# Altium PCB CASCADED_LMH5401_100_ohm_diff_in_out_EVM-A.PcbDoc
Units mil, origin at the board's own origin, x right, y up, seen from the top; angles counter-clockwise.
Board outline 1606 x 1500 mil, 6 copper layers (Top Layer L1, Layer 2 GND L2, Layer 3 V+ L3, Layer 4 V- L4, Layer 5 GND L5, Bottom Layer L6), stack 60.4 mil thick; 88 components, 31 nets, 189 pads, 288 vias.
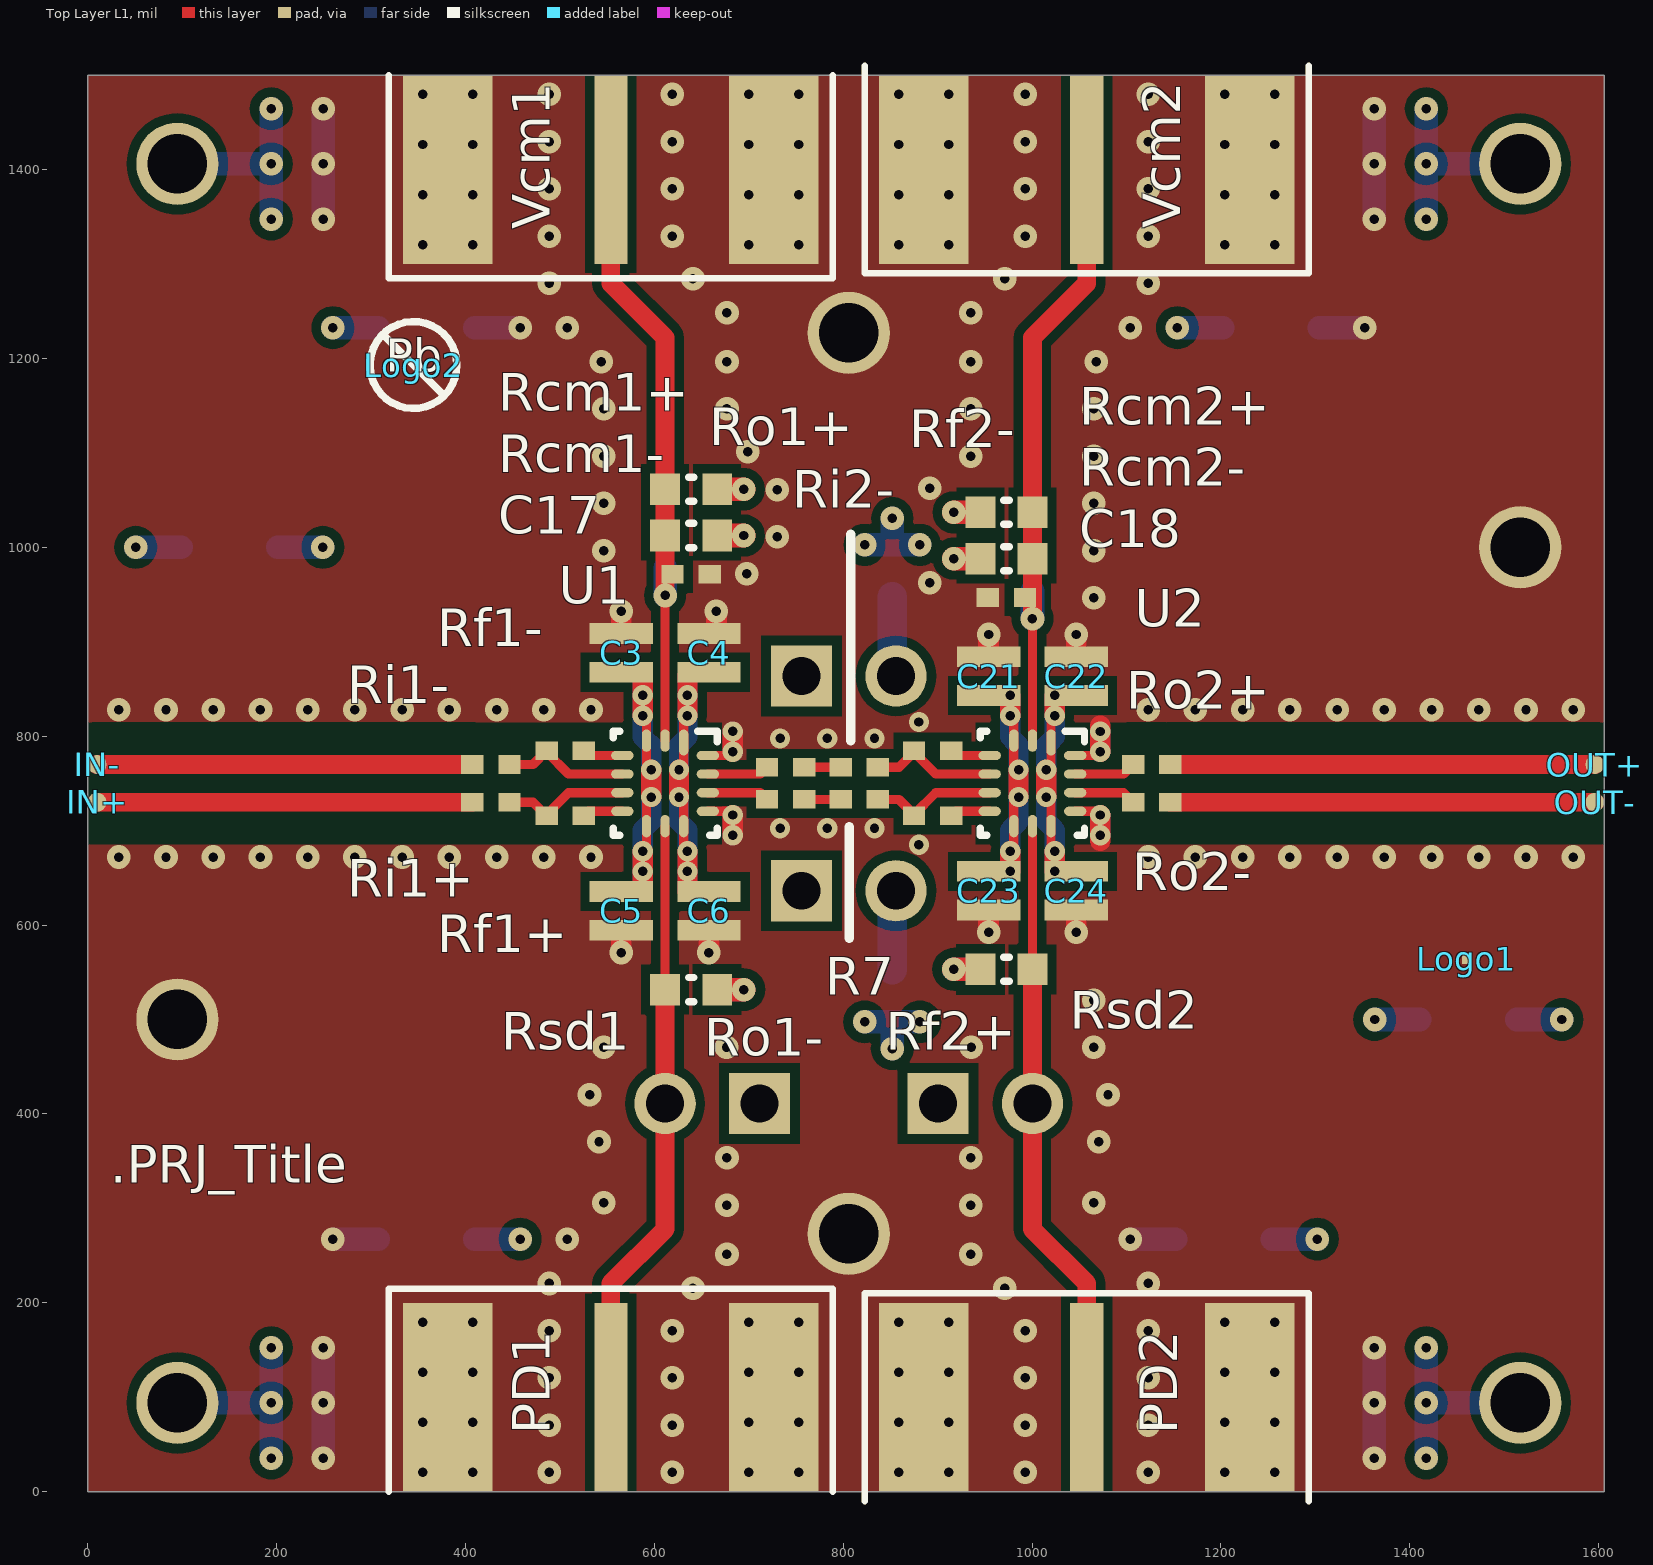
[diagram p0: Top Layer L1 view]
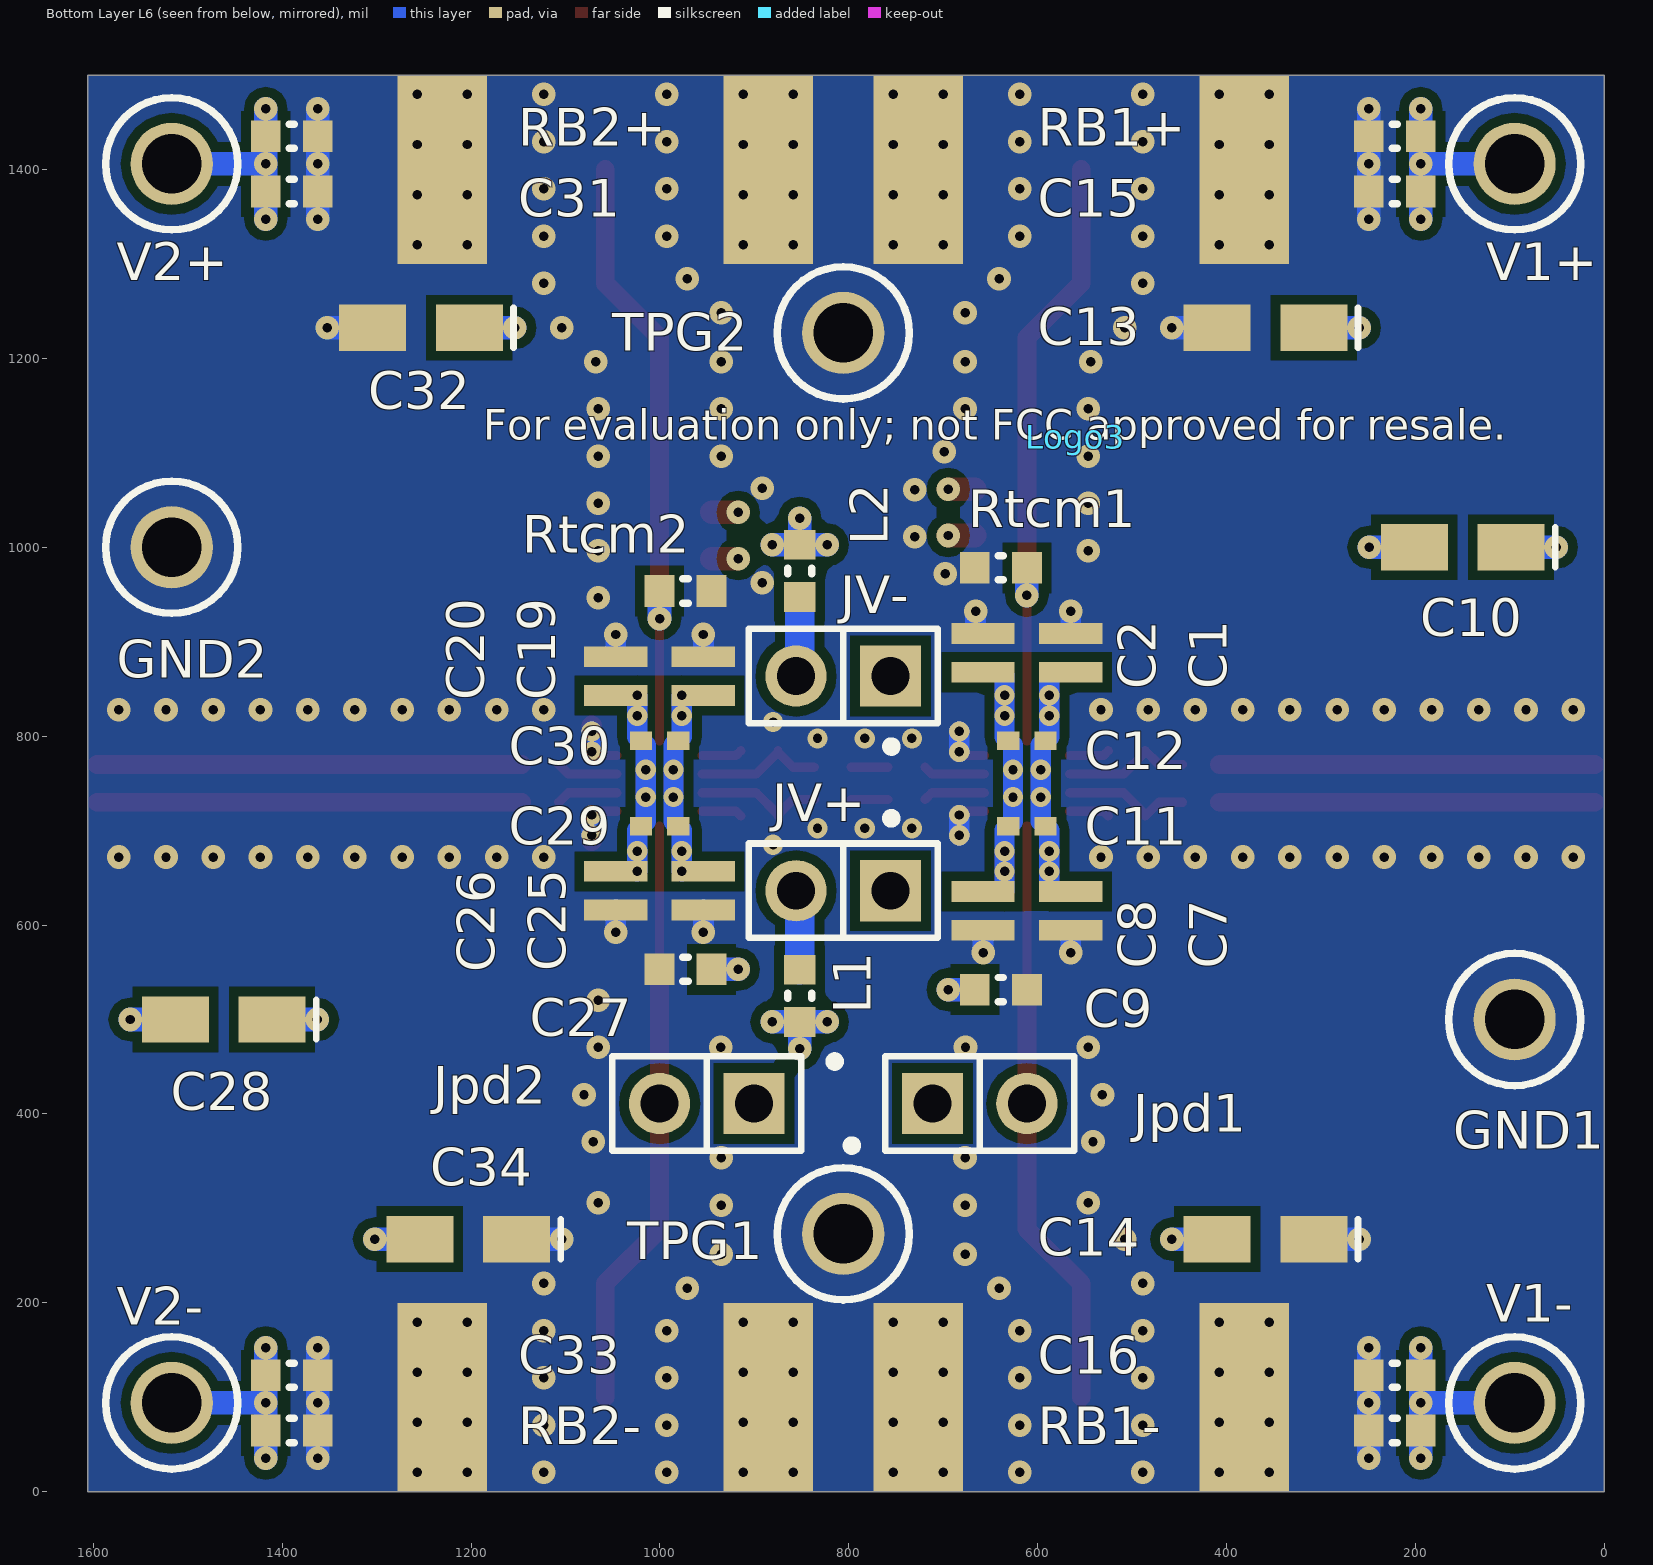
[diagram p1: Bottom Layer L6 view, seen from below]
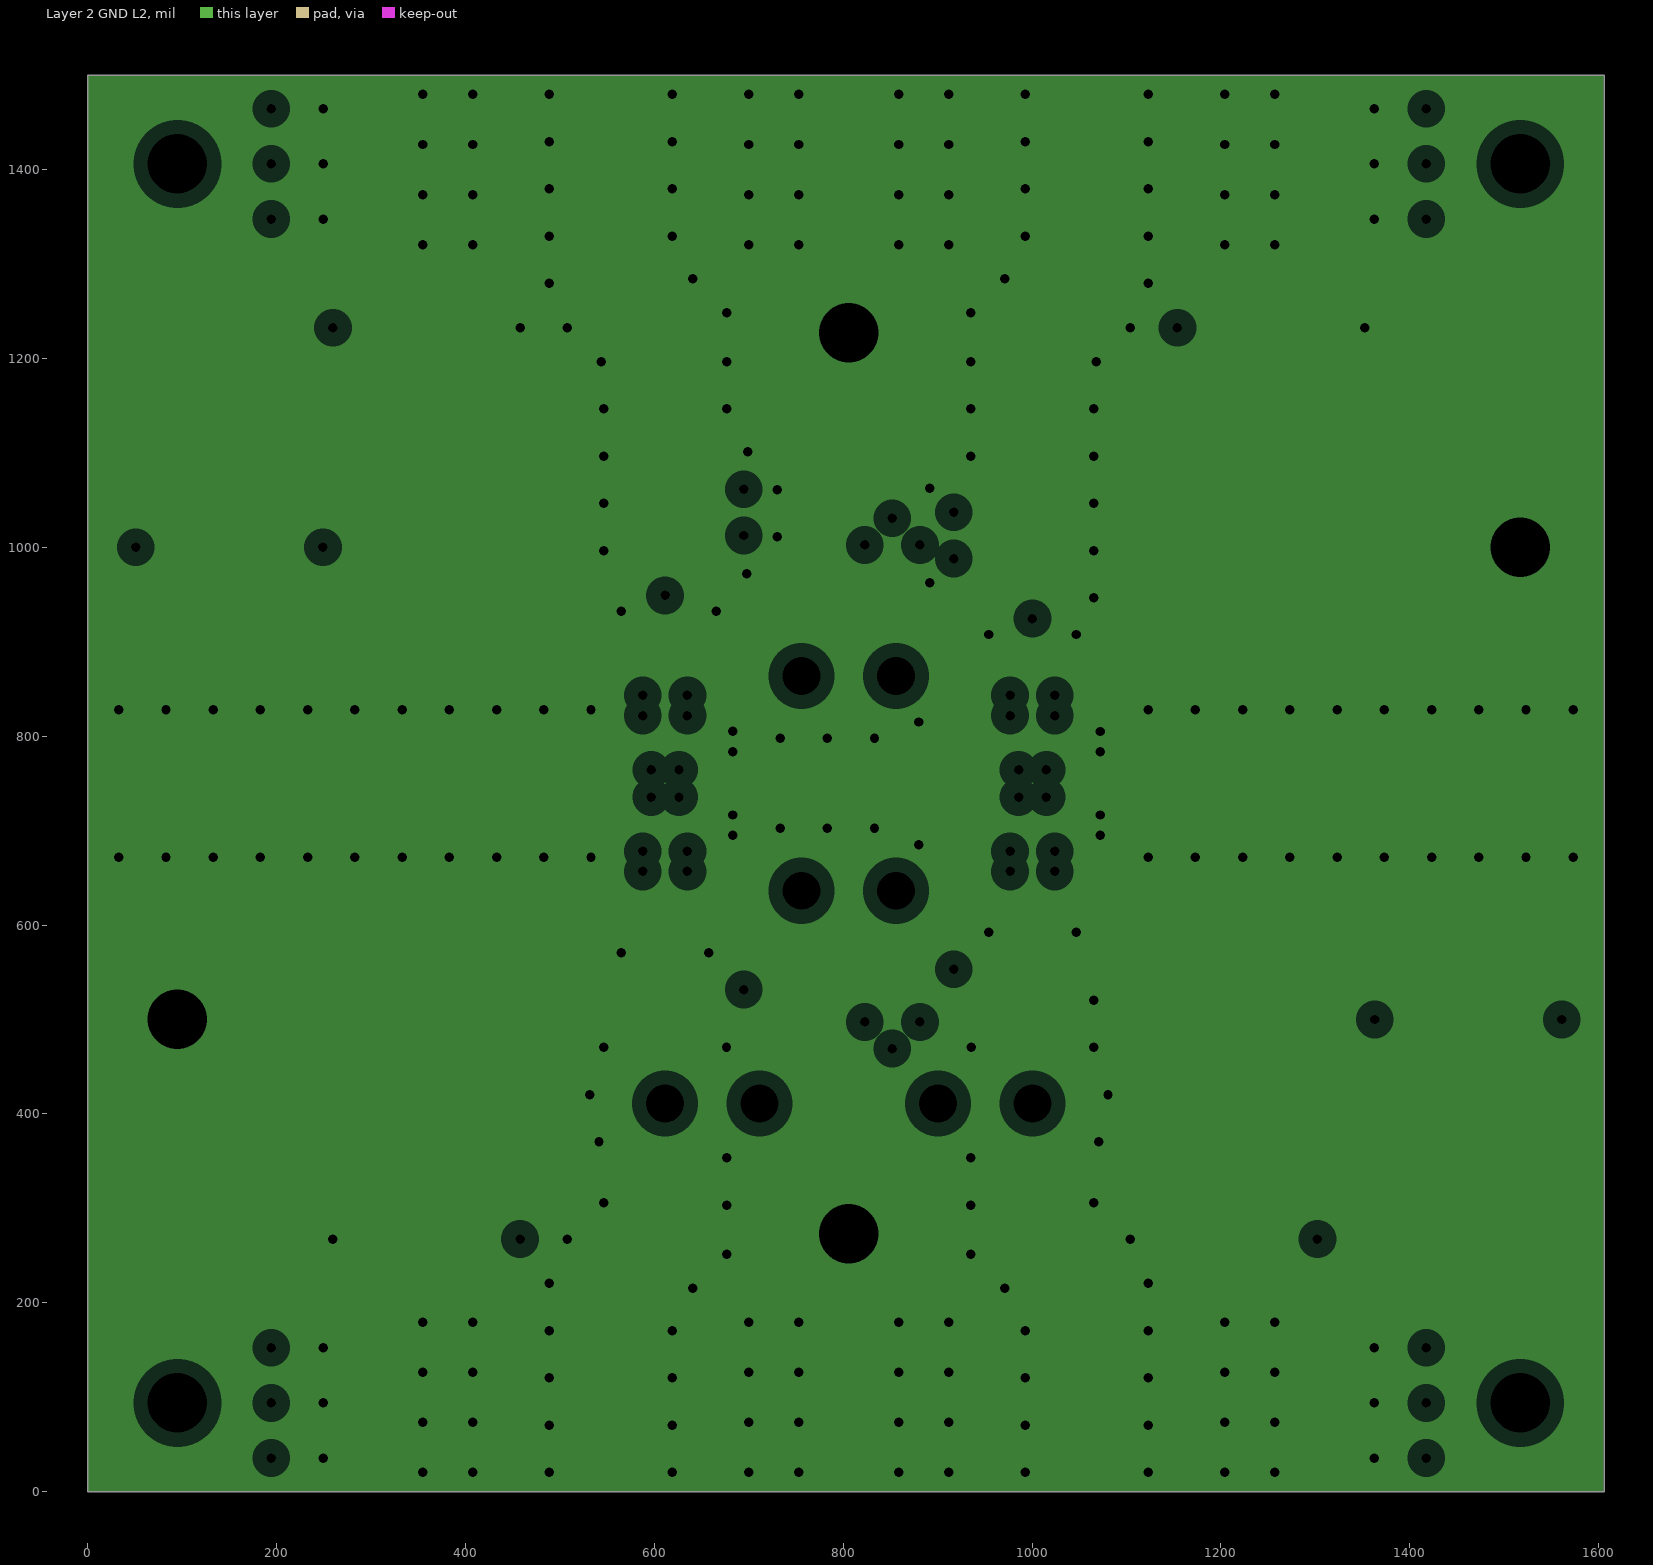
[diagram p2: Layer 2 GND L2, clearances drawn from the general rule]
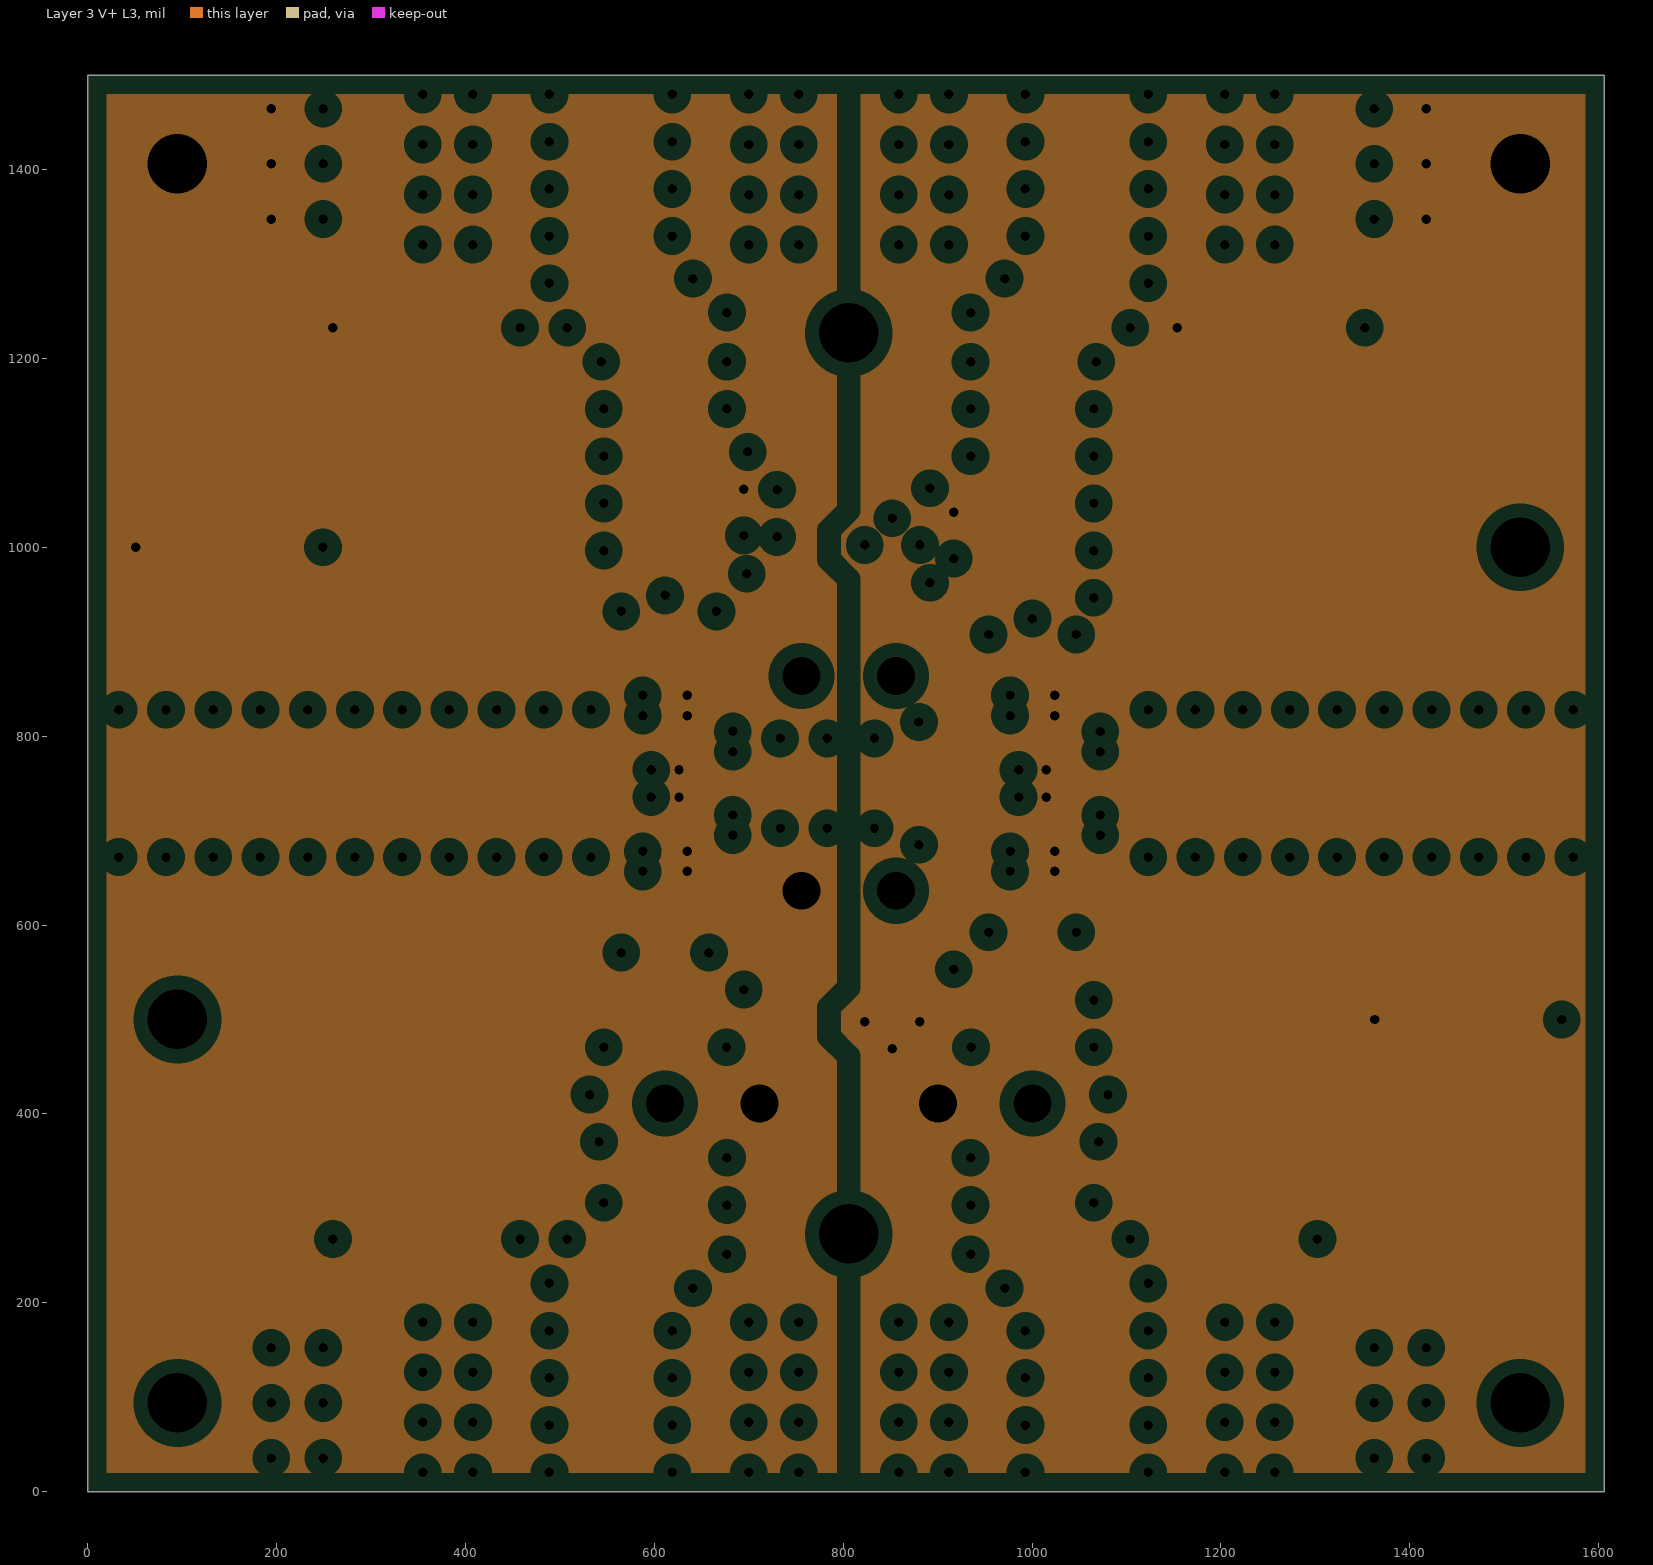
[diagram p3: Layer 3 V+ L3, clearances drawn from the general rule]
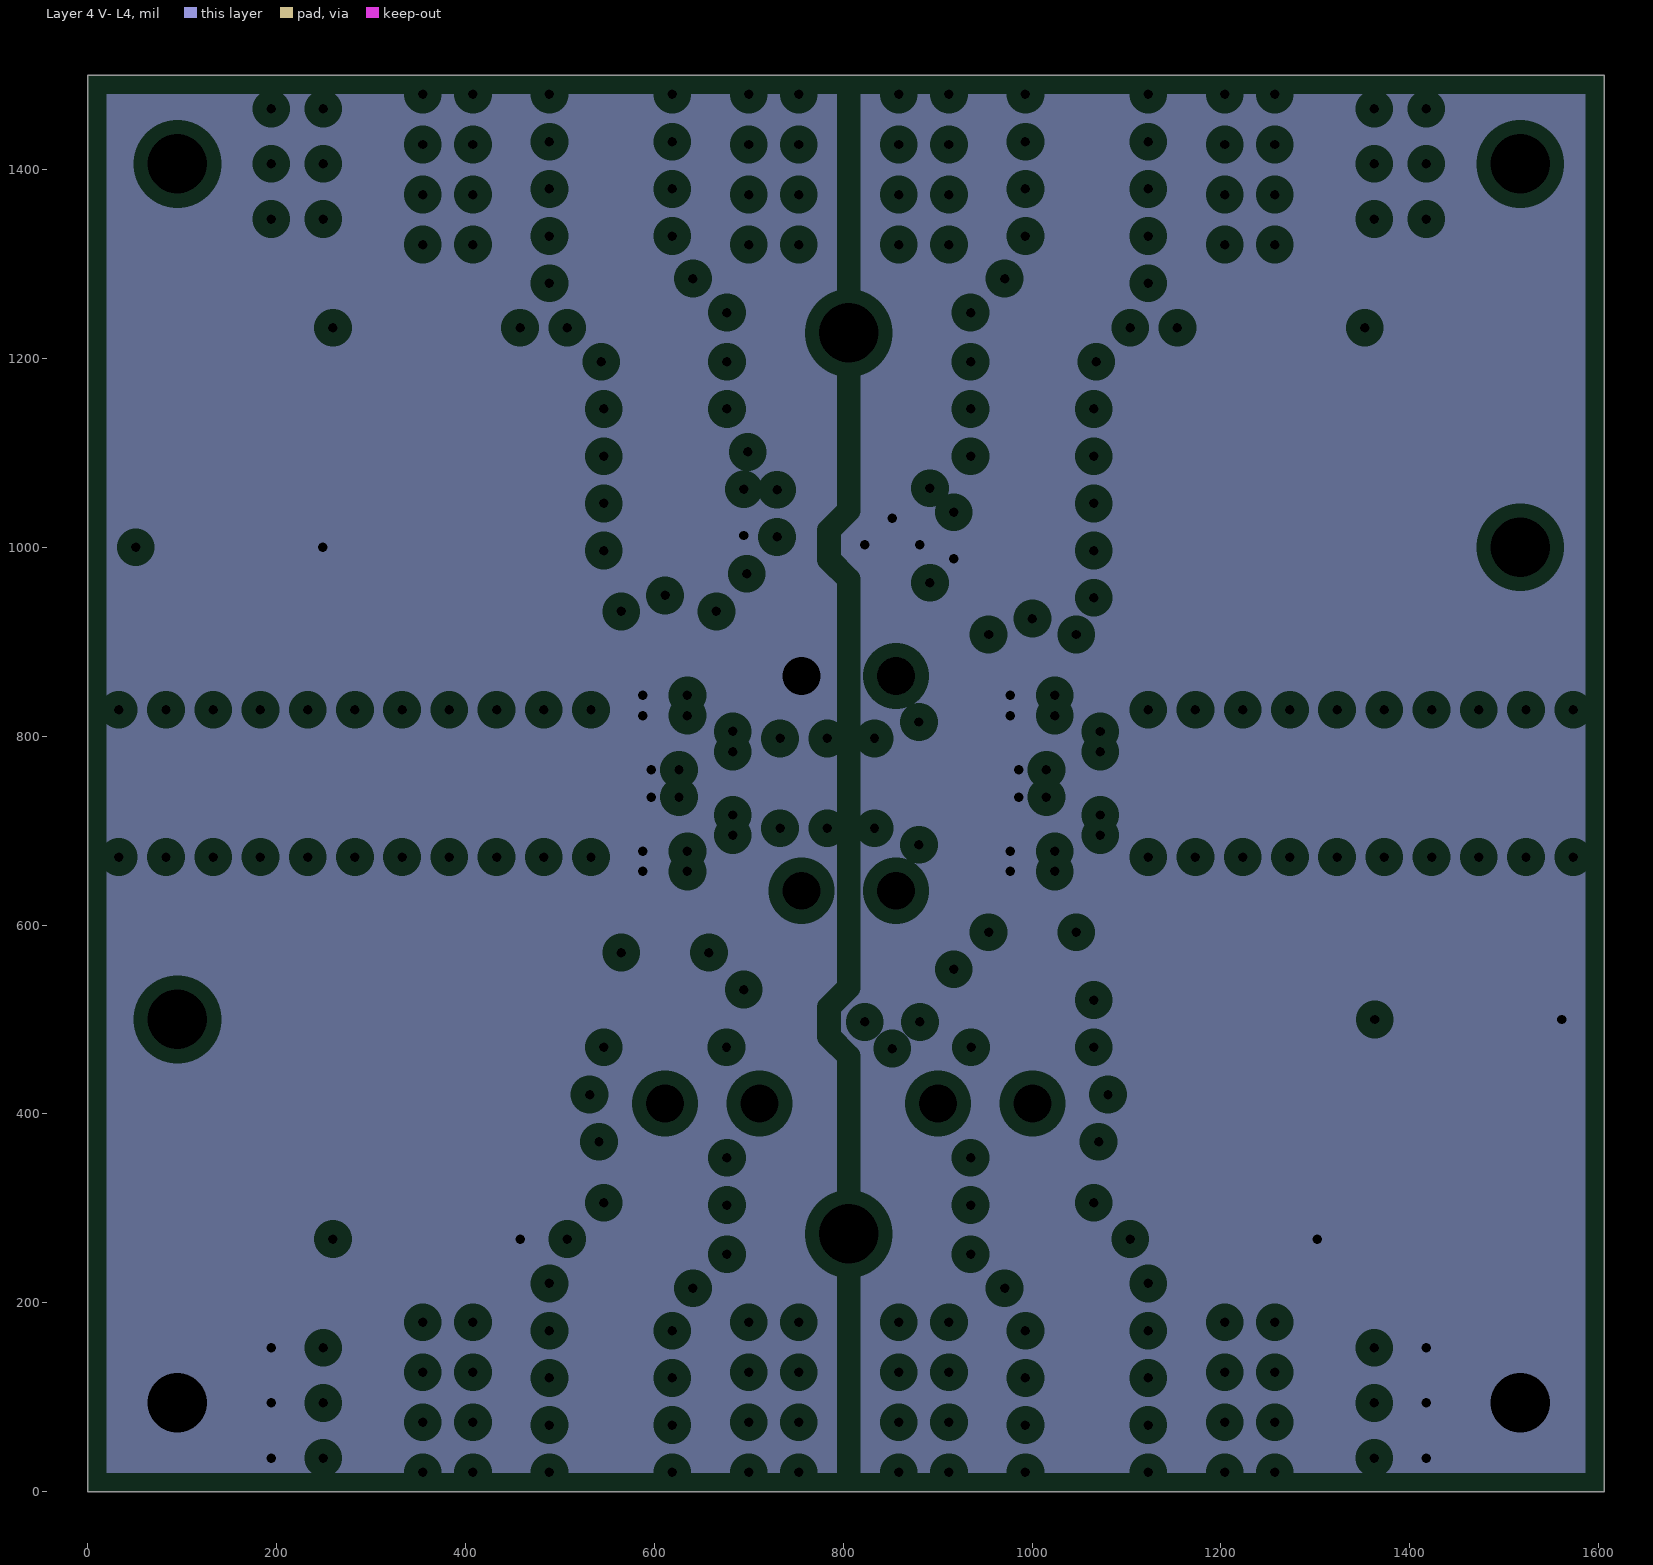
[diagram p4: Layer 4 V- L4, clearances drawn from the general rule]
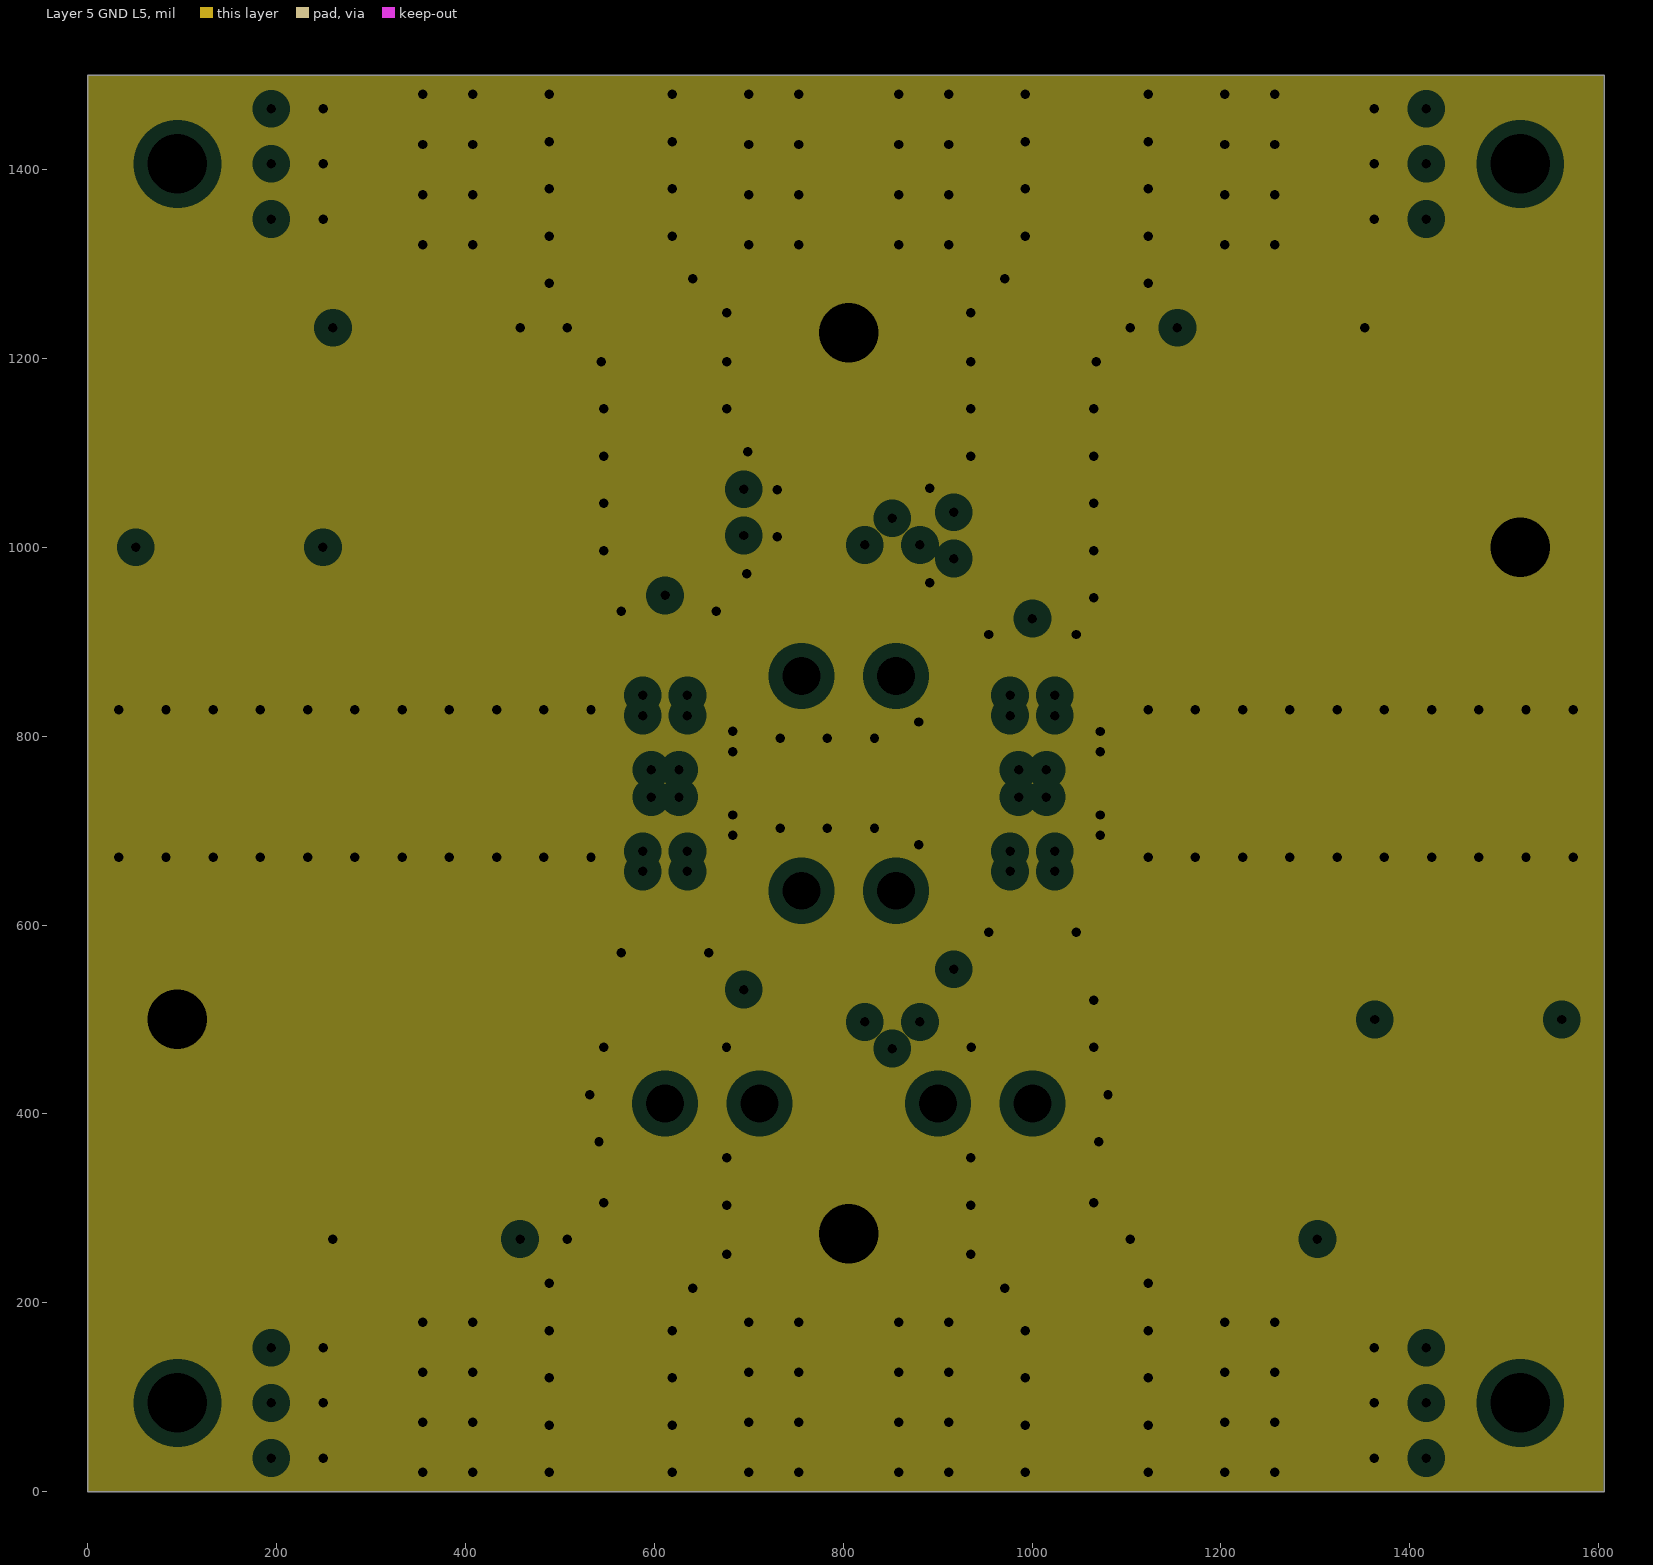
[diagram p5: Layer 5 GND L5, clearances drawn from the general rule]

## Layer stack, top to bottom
Top Solder: solder mask 0.4, Solder Resist, Dk 3.5
Top Layer L1: signal copper 1.4
Dielectric1: core 10, Rogers RO4350, Dk 3.66
Layer 2 GND L2: plane copper 1.4, net GND
Dielectric2: prepreg 10, FR406, Dk 4.8
Layer 3 V+ L3: plane copper 1.4, net (Multiple Nets)
Dielectric3: core 12, FR406, Dk 4.8
Layer 4 V- L4: plane copper 1.4, net (Multiple Nets)
Dielectric4: prepreg 10, FR406, Dk 4.8
Layer 5 GND L5: plane copper 1.4, net GND
Dielectric5: core 10, FR406, Dk 4.8
Bottom Layer L6: signal copper 1.4
Bottom Solder: solder mask 0.4, Solder Resist, Dk 3.5

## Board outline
0,0 1606,0 1606,1500 0,1500

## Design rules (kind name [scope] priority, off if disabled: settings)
AcuteAngle [All] p1: minimum=4.50000000000000E+0001 checktracksonly=FALSE
AssemblyTestPointUsage [All] p1: valid=2
Clearance Clearance_1 [InNamedPolygon('Top Layer L1-GND') vs (InNet('NetIN+_1') OR InNet('NetIN-_1') OR InNet('NetOUT-_1') OR InNet('NetOUT+_1') OR InNet('NetRtcm_1') OR InNet('NetJpd_2'))] p1: gap=35
Clearance Clearance_BoardEdge_MountingHoles [OnCopper and InComponentClass('Mounting Holes') vs IsKeepOut] p2: gap=40
Clearance Clearance_BoardEdge_Poly [OnCopper and InPoly vs IsKeepOut] p3: gap=25
Clearance Clearance_BoardEdge [OnCopper and Not InComponentClass('Logo') and not InComponentClass('FiducialMark') and not InRegion(1000,500,4000,800) and Not IsKeepout vs IsKeepOut] p4: gap=75
Clearance Clearance_Poly [InPolygon] p5: gap=10
Clearance [All] p6: gap=8
ComponentClearance ComponentClearance_Logo [InComponentClass(Logo)] p1: gap=50 collisioncheckmode=3 verticalgap=10 showdistances=FALSE
ComponentClearance ComponentClearance_ScrewToNut [(HasFootprint('NY PMS 440 0025 PH')) vs (HasFootprint('Keystone_1902C'))] p2: gap=5 collisioncheckmode=3 verticalgap=10 showdistances=FALSE
ComponentClearance ComponentClearance_MountingHoles [InComponentClass('Mounting Holes')] p3: gap=250 collisioncheckmode=3 verticalgap=100000 showdistances=FALSE
ComponentClearance ComponentClearance_SmallPassives [HasFootprint('0201*') or HasFootprint('0402*') or HasFootprint('0508') or HasFootprint('0603*') or HasFootprint('0612') or HasFootprint('0805*') or HasFootprint('0815*') or HasFootprint('0830*') or HasFootprint('1206*') or HasFootprint('1210*') or HasFootprint('1808*') or HasFootprint('1812*') or HasFootprint('1825*') or HasFootprint('2010*') or HasFootprint('2220*') or HasFootprint('2225*') or HasFootprint('2512*') or HasFootprint('2728*') or HasFootprint('3518*') or HasFootprint('3216-18*') or HasFootprint('RMS0014A*') or HasFootprint('0306*') or HasFootprint('TP_25MIL-SMT*') vs HasFootprint('0201*') or HasFootprint('0402*') or HasFootprint('0508') or HasFootprint('0603*') or HasFootprint('0612') or HasFootprint('0805*') or HasFootprint('0815*') or HasFootprint('0830*') or HasFootprint('1206*') or HasFootprint('1210*') or HasFootprint('1808*') or HasFootprint('1812*') or HasFootprint('1825*') or HasFootprint('2010*') or HasFootprint('2220*') or HasFootprint('2225*') or HasFootprint('2512*') or HasFootprint('2728*') or HasFootprint('3518*') or HasFootprint('3216-18*') or HasFootprint('RMS0014A*') or HasFootprint('0306*') or HasFootprint('TP_25MIL-SMT*')] p4: gap=10 collisioncheckmode=3 verticalgap=10 showdistances=FALSE
ComponentClearance ComponentClearance_THtoSMT [IsThruComponent vs IsSMTComponent] p5: gap=10 collisioncheckmode=3 verticalgap=0 showdistances=FALSE
ComponentClearance ComponentClearance_THtoTH [IsThruComponent vs IsThruComponent] p6: gap=35 collisioncheckmode=3 verticalgap=0 showdistances=FALSE
ComponentClearance [All] p7: gap=35 collisioncheckmode=3 verticalgap=10 showdistances=FALSE
DiffPairsRouting [All] p1: maxlimit=100 minlimit=10 mostfreqgap=10 toplayer_minwidth=15 toplayer_maxwidth=15 toplayer_prefwidth=15 bottomlayer_minwidth=15 bottomlayer_maxwidth=15 bottomlayer_prefwidth=15 maxuncoupledlength=1000
FabricationTestPointUsage TestPointUsage [All] p1: valid=2 allowmultiple=FALSE
FabricationTestpoint Testpoint [All] p1: side=3 testpointundercomponent=TRUE minsize=40 maxsize=100 preferedsize=60 minholesize=0 maxholesize=40 preferedholesize=32 testpointgrid=1 allowsidetop=TRUE allowsidebottom=TRUE usegrid=TRUE gridtolerance=0.01
FanoutControl Fanout_LCC [IsLCC] p1: bgadir=Out bgaviamode=Centered fanoutstyle=Auto fanoutdirection=Alternating viagrid=1 // Fanout_LCC (Default Rule)
FanoutControl Fanout_BGA [IsBGA] p2: bgadir=Out bgaviamode=Centered fanoutstyle=Auto fanoutdirection=Alternating viagrid=1 // Fanout_BGA (Default Rule)
FanoutControl Fanout_Default [All] p4: bgadir=Out bgaviamode=Centered fanoutstyle=Auto fanoutdirection=Alternating viagrid=1 // Fanout_Default (Default Rule)
FanoutControl Fanout_Small [(CompPinCount < 5)] p5: bgadir=Out bgaviamode=Centered fanoutstyle=Auto fanoutdirection=OutThenIn viagrid=1 // Fanout_Small (Default Rule)
HoleSize [All] p1: absolutevalues=TRUE maxlimit=251 minlimit=8 maxpercent=80.000 minpercent=20.000
MinimumAnnularRing [All] p1: minimumring=5.73
MinimumSolderMaskSliver MinimumSolderMaskSliver_Logo [InComponentClass('Logo') vs InComponentClass('Logo')] p1: minsoldermaskwidth=0.7
MinimumSolderMaskSliver [All] p2: minsoldermaskwidth=3.84
PlaneClearance [All] p1: clearance=15
PlaneConnect [All] p1: planeconnectstyle=Direct reliefexpansion=10 reliefentries=4 reliefconductorwidth=10 reliefairgap=10
PolygonConnect [All] p1: connectstyle=Direct reliefconductorwidth=10 reliefentries=4 polygonreliefangle="90 Angle" airgapwidth=10
RoutingVias [All] p1: holewidth=16 width=34 viastyle="Through Hole" minholewidth=8 minwidth=21.46 maxholewidth=40 maxwidth=65
SMDToCorner [All] p1: distance=30000
SilkToSilkClearance [All] p1: silktosilkclearance=5
SilkToSolderMaskClearance SilkscreenOverComponentPads [IsPad] p1: minsilkscreentomaskgap=5 clearancetoexposedcopper=TRUE
SolderMaskExpansion [All] p1: expansion=3
UnpouredPolygon [All] p1: allowunpoured=FALSE
Width [All] p1: maxlimit=100 minlimit=8 preferedwidth=10 checkconnectedcopper=TRUE
14 further rules are at their usual default settings.

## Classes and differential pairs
component class Header: Jpd1 Jpd2 JV+ JV-
component class 0402L: C12 C17 C18 C30
component class AssemblyNote: ZZ2 ZZ3 ZZ4
component class Logo: Logo1

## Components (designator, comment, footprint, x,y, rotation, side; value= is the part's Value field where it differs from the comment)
C1 "LLL185R71E103MA01L" 0306 565.02,888.1 r270 bottom
C2 "LLL185R71E103MA01L" 0306 657.86,888.1 r90 bottom
C3 "LLL185R71H222MA01L" 0306 565.02,888.1 r90 top
C4 "LLL185R71H222MA01L" 0306 657.86,888.1 r270 top
C5 "LLL185R71H222MA01L" 0306 565.02,614.9 r270 top
C6 "LLL185R71H222MA01L" 0306 657.86,614.9 r90 top
C7 "LLL185R71E103MA01L" 0306 565.02,614.9 r90 bottom
C8 "LLL185R71E103MA01L" 0306 657.86,614.9 r270 bottom
C9 "GRM188R71C103KA01D" 0603L 639,531.67 r180 bottom
C10 "TPSA106K010R0900" 3216-18 150,1000 r0 bottom
C11 "C1005X5R1A104K" 0402L 611.44,704.72 r0 bottom
C12 "C1005X7R1E103K" 0402L 611.44,795.28 r0 bottom
C13 "TPSA106K010R0900" 3216-18 358.83,1232.5 r0 bottom
C14 "TPSA106K010R0900" 3216-18 358.83,267.5 r0 bottom
C15 "Used in BOM report" 0603L 222,1376.77 r0 bottom
C16 "Used in BOM report" 0603L 222,123.23 r0 bottom
C17 "C1005X7R1E103K" 0402L 639,971.33 r180 top
C18 "C1005X7R1E103K" 0402L 972.88,946.87 r0 top
C19 "LLL185R71E103MA01L" 0306 954.02,863.64 r270 bottom
C20 "LLL185R71E103MA01L" 0306 1046.86,863.64 r90 bottom
C21 "LLL185R71H222MA01L" 0306 954.02,863.64 r90 top
C22 "LLL185R71H222MA01L" 0306 1046.86,863.64 r270 top
C23 "LLL185R71H222MA01L" 0306 954.02,636.36 r270 top
C24 "LLL185R71H222MA01L" 0306 1046.86,636.36 r90 top
C25 "LLL185R71E103MA01L" 0306 954.02,636.36 r90 bottom
C26 "LLL185R71E103MA01L" 0306 1046.86,636.36 r270 bottom
C27 "GRM188R71C103KA01D" 0603L 972.88,553.13 r0 bottom
C28 "TPSA106K010R0900" 3216-18 1461.88,500 r0 bottom
C29 "C1005X5R1A104K" 0402L 1000.44,704.72 r0 bottom
C30 "C1005X7R1E103K" 0402L 1000.44,795.28 r0 bottom
C31 "Used in BOM report" 0603L 1389.88,1376.77 r180 bottom
C32 "TPSA106K010R0900" 3216-18 1253.06,1232.5 r0 bottom
C33 "Used in BOM report" 0603L 1389.88,123.23 r180 bottom
C34 "TPSA106K010R0900" 3216-18 1203.06,267.5 r0 bottom
GND1 "5011" Keystone5011 95,500 r180 bottom
GND2 "5011" Keystone5011 1516.88,1000 r0 bottom
IN+ "TESTPOINT" TP_25MIL-SMT 10,730 r90 top
IN- "TESTPOINT" TP_25MIL-SMT 10,770 r90 top
Jpd1 "TSW-102-07-G-S" TSW-102-07-G-S 661.44,411 r180 bottom
Jpd2 "TSW-102-07-G-S" TSW-102-07-G-S 950.44,411 r0 bottom
JV+ "TSW-102-07-G-S" TSW-102-07-G-S 805.94,636.36 r0 bottom
JV- "TSW-102-07-G-S" TSW-102-07-G-S 805.94,863.64 r0 bottom
L1 "BLM18SG331TN1D" 0603L 852,525 r270 bottom
L2 "BLM18SG331TN1D" 0603L 852,975 r90 bottom
Logo1 "Texas Instruments" TI_Symbol_SolderMask_Small 1460,564 r0 top
Logo2 "Pb-Free Symbol" Pb-Free_Overlay_Small 345,1193 r0 top
Logo3 "FCC disclaimer" FCC_disclaimer 560,1117 r180 bottom
OUT+ "TESTPOINT" TP_25MIL-SMT 1596,770 r90 top
OUT- "TESTPOINT" TP_25MIL-SMT 1596,730 r90 top
PD1 "142-0701-851" Emerson_142-0701-851#1 553.94,100 r180 top
PD2 "142-0701-851" Emerson_142-0701-851#2 1057.94,-10 r180 top
R7 "CRCW04020000Z0ED" 0402L 817,733 r180 top
RB1+ "Used in BOM report" 0603L 222,1435.23 r180 bottom
RB1- "Used in BOM report" 0603L 222,64.77 r0 bottom
RB2+ "Used in BOM report" 0603L 1389.88,1435.23 r0 bottom
RB2- "Used in BOM report" 0603L 1389.88,64.77 r180 bottom
Rcm1+ "CRCW06031K00FKEA" 0603L 639,1061.46 r0 top
Rcm1- "CRCW06031K00FKEA" 0603L 639,1012.46 r180 top
Rcm2+ "CRCW06031K00FKEA" 0603L 972.88,1037 r180 top
Rcm2- "CRCW06031K00FKEA" 0603L 972.88,988 r0 top
Rf1+ "CRCW0402174RFKED" 0402L 505.76,715.55 r180 top
Rf1- "CRCW0402174RFKED" 0402L 505.76,784.45 r180 top
Rf2+ "CRCW0402174RFKED" 0402L 894.76,715.55 r180 top
Rf2- "CRCW0402174RFKED" 0402L 894.76,784.45 r180 top
Ri1+ "CRCW040236R5FKED" 0402L 427,730 r180 top
Ri1- "CRCW040236R5FKED" 0402L 427,770 r0 top
Ri2- "CRCW04020000Z0ED" 0402L 817,767 r0 top
Ro1+ "CRCW040240R2FKED" 0402L 739,767 r0 top
Ro1- "CRCW040240R2FKED" 0402L 739,733 r0 top
Ro2+ "CRCW040240R2FKED" 0402L 1126.69,770 r0 top
Ro2- "CRCW040240R2FKED" 0402L 1126.69,730 r0 top
Rsd1 "CRCW060349R9FKEA" 0603L 639,531.67 r180 top
Rsd2 "CRCW060349R9FKEA" 0603L 972.88,553.13 r0 top
Rtcm1 "Used in BOM report" 0603L 639,978.22 r0 bottom
Rtcm2 "Used in BOM report" 0603L 972.88,953.76 r180 bottom
TPG1 "5011" Keystone5011 805.94,273 r180 bottom
TPG2 "5011" Keystone5011 805.94,1227 r180 bottom
U1 "LMH5401IRMSR" RMS0014A 611.44,750 r270 top
U2 "LMH5401IRMSR" RMS0014A 1000.44,750 r270 top
V1+ "5010" Keystone5010 95,1406 r180 bottom
V1- "5014" Keystone5014 95,94 r180 bottom
V2+ "5010" Keystone5010 1516.88,1406 r0 bottom
V2- "5014" Keystone5014 1516.88,94 r180 bottom
Vcm1 "142-0701-851" Emerson_142-0701-851#1 553.94,1400 r0 top
Vcm2 "142-0701-851" Emerson_142-0701-851#2 1057.94,1510 r0 top
ZZ2 "These assemblies are ESD sensitive, ESD precautions shall be observed." AssemblyNote 185,3829.11 r0 top
ZZ3 "These assemblies must be clean and free from flux and all contaminants. Use of no clean flux is not acceptable." AssemblyNote 185,3740.56 r0 top
ZZ4 "These assemblies must comply with workmanship standards IPC-A-610 Class 2., unless otherwise specified." AssemblyNote 185,3652 r0 top

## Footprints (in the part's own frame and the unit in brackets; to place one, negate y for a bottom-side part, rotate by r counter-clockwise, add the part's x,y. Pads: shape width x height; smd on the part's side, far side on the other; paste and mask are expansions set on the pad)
0306 [mil] "bxl footprint"
  rect 22x67 smd: 1(-20.5,0) 2(20.5,0)
  body extent -17,-33 17,33, height 24
0402L [mm] "0402 from SM-752 data"
  rect 0.6x0.5 smd: 1(-0.5,0) 2(0.5,0)
  body extent -0.55,-0.3 0.55,0.3, height 0.6
0603L [mm] "0603 from SM-752 data"
  rect 0.8x0.85 smd: 1(-0.7,0) 2(0.7,0)
  silkscreen extent -0.07,-0.33 0.07,0.33, body extent -0.87,-0.47 0.87,0.47, height 0.85
3216-18 [mm] "Medium density IPC, based on Kemet T495 dimensions"
  rect 1.8x1.25 smd: 1(-1.3,0) 2(1.3,0)
  silkscreen extent -2.49,-0.54 -2.49,0.54, body extent -1.7,-0.9 1.7,0.9, height 1.8
AssemblyNote [mil] "Assembly Note"
Emerson_142-0701-851#1 [mil] "Johnson Components"
  rect 35x200 smd: 1(0,0)
  rect 95x200 smd: 2(-172.5,0) 3(172.5,0)
  rect 95x200 smd far side: 4(172.5,0) 5(-172.5,0)
  silkscreen extent -235,-115 235,100, body extent -190,-95 190,487, height 155
Emerson_142-0701-851#2 [mil] "Johnson Components"
  rect 35x200 smd: 1(0,-110)
  rect 95x200 smd: 2(-172.5,-110) 3(172.5,-110)
  rect 95x200 smd far side: 4(172.5,-110) 5(-172.5,-110)
  silkscreen extent -235,-220 235,0, body extent -190,-195 190,387, height 155
FCC_disclaimer [mil]
Keystone5010 [mil] "Keystone Multipurpose loops"
  round 87 hole 63: 1(0,0)
  silkscreen extent -70,-70 70,70, body extent -63,-63 63,62, height 319
Keystone5011 [mil] "Keystone Multipurpose loops"
  round 87 hole 63: 1(0,0)
  silkscreen extent -70,-70 70,70, body extent -63,-63 63,62, height 319
Keystone5014 [mil] "Keystone Multipurpose loops"
  round 87 hole 63: 1(0,0)
  silkscreen extent -70,-70 70,70, body extent -63,-63 63,62, height 319
Pb-Free_Overlay_Small [mil]
  silkscreen extent -46,-46 46,46
RMS0014A [mm] "QFN, Body 2.6x2.6mm, Pitch 0.5mm"
  oval 0.7x0.25 smd mask+0.066: 1(-1.1,0.5)
  oval 0.6x0.25 smd: 2(-1.15,0) 3(-1.15,-0.5) 8(1.15,-0.5) 9(1.15,0) 10(1.15,0.5)
  oval 0.25x0.6 smd: 4(-0.75,-1.15) 5(-0.25,-1.15) 6(0.25,-1.15) 7(0.75,-1.15) 11(0.75,1.15) 12(0.25,1.15) 13(-0.25,1.15) 14(-0.75,1.15)
  silkscreen extent -1.4,-1.4 1.4,1.4, body extent -1.3,-1.3 1.3,1.3, height 0.61
TI_Symbol_SolderMask_Small [mil]
  rect 10x10 smd paste-10 mask-10: 0(0,0)
TP_25MIL-SMT [mil]
  round 20 smd mask-2.5: 1(0,0)
TSW-102-07-G-S [mm] "Samtec 100mil, 1x2, 230 mil above insulator"
  rect 1.65x1.65 hole 1.016 mask+0: 1(-1.27,0)
  round 1.65 hole 1.016 mask+0: 2(1.27,0)
  silkscreen extent -3.57,-1.27 2.54,1.27, body extent -2.54,-1.27 2.54,1.27, height 8.38

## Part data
C1 C2 C7 C8 C19 C20 C25 C26: "CAP, CERM, 0.01uF, 25V, +/-20%, X7R, 0306"
C3 C4 C5 C6 C21 C22 C23 C24: "CAP, CERM, 2200pF, 50V, +/-20%, X7R, 0306"
C9 C27: "CAP, CERM, 0.01uF, 16V, +/-10%, X7R, 0603"
C10 C13 C14 C28 C32 C34: "CAP, TA, 10uF, 10V, +/-10%, 0.9 ohm, SMD"
C11 C29: "CAP, CERM, 0.1uF, 10V, +/-10%, X5R, 0402"
C12 C17 C18 C30: "CAP, CERM, 0.01uF, 25V, +/-10%, X7R, 0402"
C15 C16 C31 C33: library part Capacitor, "CAP, CERM, xxxF, xxV, [TempCo], xx%, [PackageReference]"
GND1 GND2 TPG1 TPG2: "Test Point, TH, Multipurpose, Black"
IN+ IN- OUT+ OUT-: "TEST POINT.  No entry in BOM."
Jpd1 Jpd2 JV+ JV-: "Header, TH, 100mil, 2x1, Gold plated, 230 mil above insulator"
L1 L2: "Ferrite Bead, 330 ohm @ 100 MHz, 1.5 A, 0603"
Logo1: library part TI_Logo, "Texas Instrument Corporate Signature"
Logo2: library part Pb-Free
Logo3: library part FCC_disclaimer, "FCC_disclaimer"
PD1 PD2 Vcm1 Vcm2: "Connector, SMT, End launch SMA 50 ohm"
R7 Ri2-: "RES, 0, 5%, 0.063 W, 0402"
RB1+ RB1- RB2+ RB2- Rtcm1 Rtcm2: library part Resistor, "RES, xxx ohm, x%, xW, [PackageReference]"
Rcm1+ Rcm1- Rcm2+ Rcm2-: "RES, 1.00k ohm, 1%, 0.1W, 0603"
Rf1+ Rf1- Rf2+ Rf2-: "RES, 174, 1%, 0.063 W, 0402"
Ri1+ Ri1-: "RES, 36.5, 1%, 0.063 W, 0402"
Ro1+ Ro1- Ro2+ Ro2-: "RES, 40.2 ohm, 1%, 0.063W, 0402"
Rsd1 Rsd2: "RES, 49.9 ohm, 1%, 0.1W, 0603"
U1 U2: "8GHz Ultra Wideband Fully Differential Amplifier, RMS0014A"
V1+ V2+: "Test Point, TH, Multipurpose, Red"
V1- V2-: "Test Point, Multipurpose, Yellow, TH"
ZZ2 ZZ3 ZZ4: library part AssemblyNote

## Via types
v1: diameter 25, hole 10, Top Layer L1 to Bottom Layer L6, tented both sides, 248 vias
v2: diameter 21.46, hole 10, Top Layer L1 to Bottom Layer L6, tented both sides, 40 vias

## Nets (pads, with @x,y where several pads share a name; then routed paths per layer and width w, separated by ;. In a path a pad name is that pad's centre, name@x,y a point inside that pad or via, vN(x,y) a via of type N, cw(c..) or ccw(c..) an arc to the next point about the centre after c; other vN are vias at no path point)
GND: C1.1 C2.2 C3.2 C4.1 C5.2 C6.1 C7.1 C8.2 C9.2 C13.2 C14.1 C15.2 C16.2 C17.1 C18.1 C19.1 C20.2 C21.2 C22.1 C23.2 C24.1 C25.1 C26.2 C27.2 C31.2 C32.2 C33.2 C34.1 GND1.1 GND2.1 Logo1.0 PD1.2 PD1.3 PD1.4 PD1.5 PD2.2 PD2.3 PD2.4 PD2.5 RB1+.1 RB1-.2 RB2+.1 RB2-.2 Rtcm1.2 Rtcm2.2 TPG1.1 TPG2.1 U1.11 U1.14 U2.11 U2.14 Vcm1.2 Vcm1.3 Vcm1.4 Vcm1.5 Vcm2.2 Vcm2.3 Vcm2.4 Vcm2.5 | length 1331.2
  Top Layer L1 w9.84: U1.11 679.23,720.47 v2(683.2,716.5) ; U1.14 679.23,779.53 v2(683.2,783.5) ; U2.11 1068.23,720.47 v2(1072.2,716.5) ; U2.14 1068.23,779.53 v2(1072.2,783.5)
  Top Layer L1 w21.46: v2@683.2,695.13 v2(683.2,716.5) ; v2(683.2,783.5) v2@683.2,804.87 ; v2@1072.2,689 v2(1072.2,716.5) ; v2(1072.2,783.5) v2@1072.2,811
  Top Layer L1 w22: v1(565.02,570.9) C5.2 ; C3.2 v1(565.02,932.1) ; v1(657.86,570.9) C6.1 ; C4.1@665.74,908.6 v1(665.74,932.1) ; v1(954.02,592.36) C23.2 ; C21.2 v1(954.02,907.64) ; v1(1046.86,592.36) C24.1 ; C22.1 v1(1046.86,907.64)
  Bottom Layer L6 w21.46: v2@683.2,695.13 v2(683.2,716.5) ; v2(683.2,783.5) v2@683.2,804.87 ; v2@1072.2,695.13 v2(1072.2,716.5) ; v2(1072.2,783.5) v2@1072.2,804.87
  Bottom Layer L6 w22: v1(565.02,570.9) C7.1 ; C1.1 v1(565.02,932.1) ; v1(657.86,570.9) C8.2 ; C2.2@665.74,908.6 v1(665.74,932.1) ; v1(954.02,592.36) C25.1 ; C19.1 v1(954.02,907.64) ; v1(1046.86,592.36) C26.2 ; C20.2 v1(1046.86,907.64)
  Bottom Layer L6 w25: v1(249.56,35.54) RB1-.2 v1(249.56,94) C16.2 v1(249.56,152.46) ; v1(249.56,1347.54) C15.2 v1(249.56,1406) RB1+.1 v1(249.56,1464.46) ; v1(259.71,267.5) C14.1 ; C13.2 v1(457.94,1232.5) ; v1(1103.94,267.5) C34.1 ; C32.2 v1(1352.17,1232.5) ; v1(1362.32,35.54) RB2-.2 v1(1362.32,94) C33.2 v1(1362.32,152.46) ; v1(1362.32,1347.54) C31.2 v1(1362.32,1406) RB2+.1 v1(1362.32,1464.46)
  other v1: 488.94,20.5 618.94,20.5 992.94,20.5 1122.94,20.5 354.94,20.5 407.94,20.5 699.94,20.5 752.94,20.5 858.94,20.5 911.94,20.5 1203.94,20.5 1256.94,20.5 488.94,70.5 618.94,70.5 992.94,70.5 1122.94,70.5 354.94,73.5 407.94,73.5 699.94,73.5 752.94,73.5 858.94,73.5 911.94,73.5 1203.94,73.5 1256.94,73.5 488.94,120.5 618.94,120.5 992.94,120.5 1122.94,120.5 354.94,126.5 407.94,126.5 699.94,126.5 752.94,126.5 858.94,126.5 911.94,126.5 1203.94,126.5 1256.94,126.5 488.94,170.5 618.94,170.5 992.94,170.5 1122.94,170.5 354.94,179.5 407.94,179.5 699.94,179.5 752.94,179.5 858.94,179.5 911.94,179.5 1203.94,179.5 1256.94,179.5 640.94,215.5 970.94,215.5 488.94,220.5 1122.94,220.5 676.94,251.5 934.94,251.5 507.94,267.5 676.94,303.5 934.94,303.5 546.44,306 1065.44,306 676.94,353.5 934.94,353.5 541.44,370.5 1070.44,370.5 531.44,420.5 1080.44,420.5 546.44,470.5 676.44,470.5 935.44,470.5 1065.44,470.5 1065.44,520.5 33,672 83,672 133,672 183,672 233,672 283,672 333,672 383,672 433,672 483,672 533,672 1123,672 1173,672 1223,672 1273,672 1323,672 1373,672 1423,672 1473,672 1523,672 1573,672 33,828 83,828 133,828 183,828 233,828 283,828 333,828 383,828 433,828 483,828 533,828 1123,828 1173,828 1223,828 1273,828 1323,828 1373,828 1423,828 1473,828 1523,828 1573,828 1065.44,946.5 891.88,962.5 698,972 546.44,996.5 1065.44,996.5 730,1011 546.44,1046.5 1065.44,1046.5 730,1061 891.88,1062.5 546.44,1096.5 934.94,1096.5 1065.44,1096.5 699,1101 546.44,1146.5 676.94,1146.5 934.94,1146.5 1065.44,1146.5 543.94,1196.5 676.94,1196.5 934.94,1196.5 1067.94,1196.5 507.94,1232.5 1103.94,1232.5 676.94,1248.5 934.94,1248.5 488.94,1279.5 1122.94,1279.5 640.94,1284.5 970.94,1284.5 354.94,1320.5 407.94,1320.5 699.94,1320.5 752.94,1320.5 858.94,1320.5 911.94,1320.5 1203.94,1320.5 1256.94,1320.5 488.94,1329.5 618.94,1329.5 992.94,1329.5 1122.94,1329.5 354.94,1373.5 407.94,1373.5 699.94,1373.5 752.94,1373.5 858.94,1373.5 911.94,1373.5 1203.94,1373.5 1256.94,1373.5 488.94,1379.5 618.94,1379.5 992.94,1379.5 1122.94,1379.5 354.94,1426.5 407.94,1426.5 699.94,1426.5 752.94,1426.5 858.94,1426.5 911.94,1426.5 1203.94,1426.5 1256.94,1426.5 488.94,1429.5 618.94,1429.5 992.94,1429.5 1122.94,1429.5 354.94,1479.5 407.94,1479.5 488.94,1479.5 618.94,1479.5 699.94,1479.5 752.94,1479.5 858.94,1479.5 911.94,1479.5 992.94,1479.5 1122.94,1479.5 1203.94,1479.5 1256.94,1479.5
  other v2: 880.2,684.98 683.2,695.04 1072.2,695.04 733.2,702.43 783.2,702.43 833.2,702.43 733.2,797.57 783.2,797.57 833.2,797.57 683.2,805.04 1072.2,804.96 880.2,815.02
NetC9_1: C9.1 Rsd1.1 | length 56.5
  Top Layer L1 w25: Rsd1.1 v1(694.81,531.67)
  Bottom Layer L6 w25: C9.1 v1(694.81,531.67)
NetC17_2: C17.2 Rcm1+.1 Rcm1-.2 Rtcm1.1 U1.2 Vcm1.1 | length 655.7
  Top Layer L1 w9.84: U1.2 v1@611.44,946.87
  Top Layer L1 w20: Vcm1.1 553.94,1279.39 611.44,1221.89 Rcm1+.1 v1(611.44,948.99)
  Bottom Layer L6 w25: v1(611.44,948.99) Rtcm1.1
NetC18_2: C18.2 Rcm2+.1 Rcm2-.2 Rtcm2.1 U2.2 Vcm2.1 | length 657.8
  Top Layer L1 w9.84: U2.2 v1(1000.44,924.52)
  Top Layer L1 w20: v1(1000.44,924.52) Rcm2+.1 1000.44,1221.89 1057.94,1279.39 Vcm2.1
  Bottom Layer L6 w25: v1(1000.44,924.52) Rtcm2.1
NetC27_1: C27.1 Rsd2.1 | length 56.5
  Top Layer L1 w25: v1(917.08,553.13) Rsd2.1
  Bottom Layer L6 w25: v1(917.08,553.13) C27.1
NetIN+_1: IN+.1 Ri1+.2 | length 397.3
  Top Layer L1 w20: IN+.1 Ri1+.2
NetIN-_1: IN-.1 Ri1-.1 | length 397.3
  Top Layer L1 w20: IN-.1 Ri1-.1
NetJpd1_2: Jpd1.2 PD1.1 Rsd1.2 U1.9 | length 628.5
  Top Layer L1 w9.84: Rsd1.2 U1.9
  Top Layer L1 w20: PD1.1 553.94,220.61 611.44,278.11 Jpd1.2 Rsd1.2
NetJpd2_2: Jpd2.2 PD2.1 Rsd2.2 U2.9 | length 628.5
  Top Layer L1 w9.84: Rsd2.2 U2.9
  Top Layer L1 w20: Rsd2.2 Jpd2.2 1000.44,278.11 1057.94,220.61 PD2.1
NetJV+_2: JV+.2 L1.1 | length 85.4
  Bottom Layer L6 w31.5: L1.1 852,632.42 JV+.2
NetJV-_2: JV-.2 L2.1 | length 85.4
  Bottom Layer L6 w31.5: L2.1 852,867.58 JV-.2
NetOUT+_1: OUT+.1 Ro2+.2 | length 449.6
  Top Layer L1 w20: Ro2+.2 OUT+.1
NetOUT-_1: OUT-.1 Ro2-.2 | length 449.6
  Top Layer L1 w20: Ro2-.2 OUT-.1
NetR7_1: R7.1 Rf2+.2 U2.6 | length 136.2
  Top Layer L1 w9.84: R7.1 859.16,733 Rf2+.2@875.08,717.08 ; Rf2+.2 Rf2+.2@875.08,717.08 ; U2.6 898.16,740.16 Rf2+.2@875.08,717.08
NetR7_2: R7.2 Ro1-.2 | length 38.6
  Top Layer L1 w9.84: Ro1-.2 R7.2
NetRf1+_1: Rf1+.1 U1.7 | length 42.8
  Top Layer L1 w9.84: Rf1+.1 530.37,720.47 U1.7
NetRf1+_2: Rf1+.2 Ri1+.1 U1.6 | length 136.6
  Top Layer L1 w9.84: Ri1+.1 471.63,730 Rf1+.2 486.08,717.08 509.16,740.16 U1.6
NetRf1-_1: Rf1-.1 U1.4 | length 42.8
  Top Layer L1 w9.84: Rf1-.1 530.37,779.53 U1.4
NetRf1-_2: Rf1-.2 Ri1-.2 U1.5 | length 136.6
  Top Layer L1 w9.84: Ri1-.2 471.63,770 Rf1-.2 486.08,782.92 509.16,759.84 U1.5
NetRf2+_1: Rf2+.1 U2.7 | length 42.8
  Top Layer L1 w9.84: Rf2+.1 919.37,720.47 U2.7
NetRf2-_1: Rf2-.1 U2.4 | length 42.8
  Top Layer L1 w9.84: Rf2-.1 919.37,779.53 U2.4
NetRf2-_2: Rf2-.2 Ri2-.2 U2.5 | length 136.2
  Top Layer L1 w9.84: Ri2-.2 859.16,767 Rf2-.2@875.08,782.92 ; Rf2-.2 Rf2-.2@875.08,782.92 ; U2.5 898.16,759.84 Rf2-.2@875.08,782.92
NetRi2-_1: Ri2-.1 Ro1+.2 | length 38.6
  Top Layer L1 w9.84: Ro1+.2 Ri2-.1
NetRo1+_1: Ro1+.1 U1.13 | length 65.6
  Top Layer L1 w9.84: U1.13 712.16,759.84 Ro1+.1
NetRo1-_1: Ro1-.1 U1.12 | length 65.6
  Top Layer L1 w9.84: U1.12 712.16,740.16 Ro1-.1
NetRo2+_1: Ro2+.1 U2.13 | length 65.5
  Top Layer L1 w9.84: U2.13 1096.85,759.84 Ro2+.1
NetRo2-_1: Ro2-.1 U2.12 | length 65.5
  Top Layer L1 w9.84: U2.12 1096.85,740.16 Ro2-.1
V1+: C2.1 C4.2 C6.2 C8.1 C10.1 C11.2 C12.2 C13.1 C15.1 Jpd1.1 JV+.1 RB1+.2 Rcm1+.2 U1.1 U1.10 V1+.1 | length 904.4
  Top Layer L1 w9.84: v2(626.17,735.53) 631.13,730.58 U1.10 631.13,682.21 v2(635.09,678.24) ; v2(626.17,764.47) 631.13,769.42 631.13,817.79 v2(635.09,821.76)
  Top Layer L1 w19.68: C6.2@635.09,635.4 C6.2 ; C4.2@635.09,867.6 C4.2
  Top Layer L1 w21.46: v2(626.17,735.53) v2(626.17,764.47) ; C6.2@635.09,635.32 v2@635.09,656.7 ; v2@635.09,656.86 v2(635.09,678.24) ; v2(635.09,821.76) v2@635.09,843.14 ; v2(635.09,843.22) C4.2@635.09,864.6
  Top Layer L1 w25: Rcm1+.2 v1(694.81,1061.46)
  Bottom Layer L6 w19.68: C8.1@635.09,635.4 C8.1 ; C2.1@635.09,867.6 C2.1
  Bottom Layer L6 w21.46: C8.1@635.09,635.49 635.09,656.86 v2(635.09,678.24) 635.09,700.76 C11.2 626.17,709.68 v2(626.17,735.53) v2(626.17,764.47) 626.17,790.32 C12.2 635.09,799.24 v2(635.09,821.76) v2@635.09,843.14 ; v2(635.09,843.22) C2.1@635.09,864.6
  Bottom Layer L6 w25: v1(50.89,1000) C10.1 ; V1+.1 v1(194.44,1406) ; v1(194.44,1347.54) C15.1 v1(194.44,1406) ; v1(194.44,1464.46) RB1+.2 v1(194.44,1406) ; v1(259.71,1232.5) C13.1
  other v2: 635.09,656.78
V1-: C1.2 C3.1 C5.1 C7.2 C10.2 C11.1 C12.1 C14.2 C16.1 JV-.1 RB1-.1 Rcm1-.1 U1.3 U1.8 V1-.1 | length 904.4
  Top Layer L1 w9.84: v2(587.79,678.24) 591.76,682.21 U1.8 591.76,730.58 v2(596.71,735.53) ; v2(587.79,821.76) 591.76,817.79 U1.3 591.76,769.42 v2(596.71,764.47)
  Top Layer L1 w19.68: C5.1 C5.1@587.79,635.4 ; C3.1 C3.1@587.79,867.6
  Top Layer L1 w21.46: C5.1@587.79,635.32 v2@587.79,656.7 ; v2@587.79,656.86 v2(587.79,678.24) ; v2(587.79,821.76) v2@587.79,843.14 ; v2(587.79,843.22) C3.1@587.79,864.6 ; v2(596.71,735.53) v2(596.71,764.47)
  Top Layer L1 w25: Rcm1-.1 v1(694.81,1012.46)
  Bottom Layer L6 w19.68: C7.2 C7.2@587.79,635.4 ; C1.2 C1.2@587.79,867.6
  Bottom Layer L6 w21.46: C7.2@587.79,635.49 587.79,656.86 v2(587.79,678.24) 587.79,700.76 C11.1 596.71,709.68 v2(596.71,735.53) v2(596.71,764.47) 596.71,790.32 C12.1 587.79,799.24 v2(587.79,821.76) v2@587.79,843.14 ; v2(587.79,843.22) C1.2@587.79,864.6
  Bottom Layer L6 w25: V1-.1 v1(194.44,94) ; v1(194.44,35.54) RB1-.1 v1(194.44,94) ; v1(194.44,152.46) C16.1 v1(194.44,94) ; C10.2 v1(249.11,1000) ; C14.2 v1(457.94,267.5)
  other v2: 587.79,656.78
V2+: C20.1 C22.2 C24.2 C26.1 C28.1 C29.2 C30.2 C31.1 C32.1 Jpd2.1 L1.2 RB2+.2 Rcm2+.2 U2.1 U2.10 V2+.1 | length 905.6
  Top Layer L1 w9.84: v2(1015.17,735.53) 1020.13,730.58 U2.10 1020.13,682.21 v2(1024.09,678.24) ; v2(1015.17,764.47) 1020.13,769.42 1020.13,795.28 1020.13,817.79 v2(1024.09,821.76)
  Top Layer L1 w19.68: C24.2@1024.09,656.86 C24.2 ; C22.2@1024.09,843.14 C22.2
  Top Layer L1 w21.46: v2(1015.17,735.53) v2(1015.17,764.47) ; C24.2@1024.09,656.86 v2(1024.09,678.24) ; v2(1024.09,821.76) C22.2@1024.09,843.14
  Top Layer L1 w25: v1(917.07,1037) Rcm2+.2
  Bottom Layer L6 w19.68: C26.1@1024.09,656.86 C26.1 ; C20.1@1024.09,843.14 C20.1
  Bottom Layer L6 w21.46: C26.1@1024.09,656.86 v2(1024.09,678.24) 1024.09,700.76 C29.2 1015.17,709.68 v2(1015.17,735.53) v2(1015.17,764.47) 1015.17,790.32 C30.2 1024.09,799.24 v2(1024.09,821.76) C20.1@1024.09,843.14
  Bottom Layer L6 w25: v1(822.77,497.44) L1.2 ; v1@852.06,469.19 L1.2 ; v1(881.23,497.44) L1.2 ; v1(1153.94,1232.5) C32.1 ; v1(1362.77,500) C28.1 ; v1(1417.44,1347.54) C31.1 v1(1417.44,1406) ; v1(1417.44,1464.46) RB2+.2 v1(1417.44,1406) ; V2+.1 v1(1417.44,1406)
  other v1: 852,469.19
  other v2: 1024.09,656.78 1024.09,843.22
V2-: C19.2 C21.1 C23.1 C25.2 C28.2 C29.1 C30.1 C33.1 C34.2 L2.2 RB2-.1 Rcm2-.1 U2.3 U2.8 V2-.1 | length 905.6
  Top Layer L1 w9.84: v2(976.79,678.24) 980.76,682.21 U2.8 980.76,730.58 v2(985.71,735.53) ; v2(976.79,821.76) 980.76,817.79 U2.3 980.76,769.42 v2(985.71,764.47)
  Top Layer L1 w19.68: C23.1 C23.1@976.79,656.86 ; C21.1 C21.1@976.79,843.14
  Top Layer L1 w21.46: C23.1@976.79,656.86 v2(976.79,678.24) ; v2(976.79,821.76) C21.1@976.79,843.14 ; v2(985.71,735.53) v2(985.71,764.47)
  Top Layer L1 w25: v1(917.07,988) Rcm2-.1
  Bottom Layer L6 w19.68: C25.2 C25.2@976.79,656.86 ; C19.2 C19.2@976.79,843.14
  Bottom Layer L6 w21.46: C25.2@976.79,656.86 v2(976.79,678.24) 976.79,700.76 C29.1 985.71,709.68 v2(985.71,735.53) v2(985.71,764.47) 985.71,790.32 C30.1 976.79,799.24 v2(976.79,821.76) C19.2@976.79,843.14
  Bottom Layer L6 w25: v1(822.77,1002.56) L2.2 ; v1@851.94,1030.81 L2.2 ; v1(881.23,1002.56) L2.2 ; C34.2 v1(1302.17,267.5) ; v1(1417.44,35.54) RB2-.1 v1(1417.44,94) ; v1(1417.44,152.46) C33.1 v1(1417.44,94) ; C28.2 v1(1561,500) ; V2-.1 v1(1417.44,94)
  other v1: 852,1030.81
  other v2: 976.79,656.78 976.79,843.22

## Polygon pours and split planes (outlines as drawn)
GND on Top Layer L1 "Top Layer L1-GND" (solid, remove dead copper, pour order 3): 0,0 0,1500 1606,1500 1606,0
GND on Bottom Layer L6 "Bottom Layer L6-GND" (solid, remove dead copper, pour order 4): 0,0 0,1500 1606,1500 1606,0
GND on Layer 2 GND L2 (split plane): 1605.95,0.05 0.05,0.05 0.05,1499.95 1605.95,1499.95
V2+ on Layer 3 V+ L3 (split plane): 1585.9,20.1 818.5,20.1 818.5,461.06 818.26,463.51 817.55,465.87 816.38,468.04 814.82,469.94 797.56,487.2 797.56,507.68 814.82,524.94 816.38,526.84 817.55,529.02 818.26,531.37 818.5,533.82 818.5,966.18 818.26,968.63 817.55,970.98 816.38,973.16 814.82,975.06 797.56,992.32 797.56,1012.8 814.82,1030.06 816.38,1031.96 817.55,1034.13 818.26,1036.49 818.5,1038.94 818.5,1479.9 1585.9,1479.9
V1+ on Layer 3 V+ L3 (split plane): 793.38,1044.14 776.12,1026.88 774.56,1024.98 773.4,1022.81 772.68,1020.45 772.44,1018 772.44,987.12 772.68,984.67 773.4,982.31 774.56,980.14 776.12,978.24 793.38,960.97 793.38,539.03 776.12,521.76 774.56,519.86 773.4,517.69 772.68,515.33 772.44,512.88 772.44,482 772.68,479.55 773.4,477.19 774.56,475.02 776.12,473.12 793.38,455.86 793.38,20.1 20.1,20.1 20.1,1479.9 793.38,1479.9
V2- on Layer 4 V- L4 (split plane): 1585.9,20.1 818.5,20.1 818.5,461.06 818.26,463.51 817.55,465.87 816.38,468.04 814.82,469.94 797.56,487.2 797.56,507.68 814.82,524.94 816.38,526.84 817.55,529.02 818.26,531.37 818.5,533.82 818.5,966.18 818.26,968.63 817.55,970.98 816.38,973.16 814.82,975.06 797.56,992.32 797.56,1012.8 814.82,1030.06 816.38,1031.96 817.55,1034.13 818.26,1036.49 818.5,1038.94 818.5,1479.9 1585.9,1479.9
V1- on Layer 4 V- L4 (split plane): 793.38,1044.14 776.12,1026.88 774.56,1024.98 773.4,1022.81 772.68,1020.45 772.44,1018 772.44,987.12 772.68,984.67 773.4,982.31 774.56,980.14 776.12,978.24 793.38,960.97 793.38,539.03 776.12,521.76 774.56,519.86 773.4,517.69 772.68,515.33 772.44,512.88 772.44,482 772.68,479.55 773.4,477.19 774.56,475.02 776.12,473.12 793.38,455.86 793.38,20.1 20.1,20.1 20.1,1479.9 793.38,1479.9
GND on Layer 5 GND L5 (split plane): 1605.95,0.05 0.05,0.05 0.05,1499.95 1605.95,1499.95

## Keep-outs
Keep-Out Layer:
  text ".Layer_Name" at 577,-858.49 h60

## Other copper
Top Layer L1:
  pour cut-out: 1157.76,814.84 1157.76,685.16 939.88,685.16 939.88,814.84
  pour cut-out: 454.13,814.84 454.13,685.16 672,685.16 672,814.84
  text ".Layer_Name" at 577,-858.49 h60
Bottom Layer L6:
  text ".Layer_Name" at 577,-858.49 h60
Layer 2 GND L2 (plane layer: these items are gaps in the copper):
  text ".Layer_Name" at 577,-858.49 h60
Layer 3 V+ L3 (plane layer: these items are gaps in the copper):
  lines w25: 805.94,0 805.94,461.06 785,482 785,512.88 805.94,533.82 805.94,966.18 785,987.12 785,1018 805.94,1038.94 805.94,1500
  text ".Layer_Name" at 577,-858.49 h60
Layer 4 V- L4 (plane layer: these items are gaps in the copper):
  lines w10: 0,1500 1606,1500
  lines w25: 805.94,0 805.94,461.06 785,482 785,512.88 805.94,533.82 805.94,966.18 785,987.12 785,1018 805.94,1038.94 805.94,1500
  text ".Layer_Name" at 577,-858.49 h60
Layer 5 GND L5 (plane layer: these items are gaps in the copper):
  text ".Layer_Name" at 577,-858.49 h60

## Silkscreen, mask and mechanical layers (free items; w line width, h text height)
Top Overlay:
  lines w10: 806.23,586 806.23,704 ; 808.23,795 808.23,1014
  text ".PRJ_Title" at 24,327 h40
  text ".Layer_Name" at 577,-858.49 h60
Bottom Overlay:
  text ".Layer_Name" at 577,-858.49 h60
Top Paste:
  text ".Layer_Name" at 577,-858.49 h60
Bottom Paste:
  text ".Layer_Name" at 577,-858.49 h60
Top Solder:
  lines w9.84: 875.08,717.08 898.16,740.16 955.17,740.16 ; 875.08,782.92 898.16,759.84 955.17,759.84
  lines w10.84: 486.08,717.08 509.16,740.16 566.17,740.16 ; 486.08,782.92 509.16,759.84 566.17,759.84 ; 875.08,717.08 898.16,740.16 955.17,740.16 ; 875.08,782.92 898.16,759.84 955.17,759.84
  lines w15.84: 486.08,715.55 486.08,717.08 ; 486.08,782.92 486.08,784.45 ; 656.72,740.16 712.16,740.16 719.32,733 ; 656.72,759.84 712.16,759.84 719.32,767 ; 758.69,733 797.31,733 ; 758.69,767 797.32,767 ; 836.68,733 859.16,733 875.08,717.08 ; 836.69,767 859.16,767 875.08,782.92 ; 1045.72,740.16 1096.85,740.16 1107.01,730 ; 1045.72,759.84 1096.85,759.84 1107.01,770
  lines w26: 10,730 407.31,730 ; 10,770 407.31,770 ; 1146.38,730 1596,730 ; 1146.38,770 1596,770
  text ".Layer_Name" at 577,-858.49 h60
  text ".Layer_Name" at 577,-858.49 h60
Bottom Solder:
  text ".Layer_Name" at 577,-858.49 h60
Drill Guide:
  text ".Layer_Name" at 577,-858.49 h60
M1 Board Outline:
  the board outline again, w10
  text ".Layer_Name" at 577,-858.49 h60
M2 Board Dimensions:
  rectangle: 124.5,-410.5 499.5,-285.5
  rectangle: -0.5,-285.5 124.5,-160.5
  lines w7: -0.5,-285.5 999.5,-285.5 ; 124.5,-410.5 124.5,-160.5 ; 249.5,-410.5 249.5,-160.5 ; 499.5,-410.5 499.5,-160.5 ; 749.5,-410.5 749.5,-160.5 ; -0.5,-410.5 -0.5,-160.5 999.5,-160.5 999.5,-410.5 -0.5,-410.5
  lines w10: -0.5,-475.5 -0.5,-455.5 ; 59.5,-485.5 -0.5,-465.5 ; 59.5,-445.5 -0.5,-465.5 ; 223.58,-465.5 -0.5,-465.5 ; 775.42,-465.5 999.5,-465.5 ; 939.5,-485.5 999.5,-465.5 ; 939.5,-445.5 999.5,-465.5 ; 999.5,-475.5 999.5,-455.5
  text "1000 (mil)" at 233.58,-501.49 h60
  text ".Layer_Name" at 577,-858.49 h60
M3 3D STEP Top:
  text ".Layer_Name" at 577,-858.49 h60
M4 3D STEP Bottom:
  text ".Layer_Name" at 577,-858.49 h60
M5 Assembly Top:
  lines w10: -292,-930.17 6308,-930.17 ; -292,-726.83 6310,-726.83 ; -292,-523.5 -292,-1133.5 3713,-1133.5 6310,-1133.5 6310,-523.5 -291.5,-523.5 -291.5,-1133.5 1284,-1133.5 ; 2173,-1133.5 2173,-523.5 ; 3440,-726.83 3440,-523.5 ; 4280,-726.83 4280,-523.5 ; 4902,-1140 4902,-937.17
  text "COMPONENTS MARKED 'DNP' SHOULD NOT BE POPULATED." at 1153.5,-318.5 h60
  text "ASSEMBLY VARIANT:" at 1153,-434 h60
  text ".VariantName" at 2189,-434 h60
  text "PCB VIEWED FROM TOP SIDE" at -228.5,-655.67 h60
  text "BOARD #:" at 2248,-655.67 h60
  text ".PRJ_Number" at 2793.5,-655.67 h60
  text "REV:" at 3638,-655.67 h60
  text ".PCB_Rev" at 3929.5,-655.67 h60
  text "SVN REV:" at 4476,-655.67 h60
  text ".VersionControl_RevNumber" at 4982,-655.67 h60
  text "IGNORE ->" at -228.5,-858.49 h60
  text "PLOT NAME =" at -228.5,-1064.34 h60
  text ".plot_File_Name" at 577,-1064.34 h60
  text "GENERATED    :" at 2250,-1064.34 h60
  text ".Print_Date" at 3119.5,-1064.34 h60
  text ".Print_Time" at 3848.5,-1064.34 h60
  text "TEXAS INSTRUMENTS" at 5113,-1064.34 h60
M6 Assembly Bottom:
  lines w10: -292.5,-727.33 6309.5,-727.33 ; -290.5,-930.67 6309.5,-930.67 ; 1115.5,-1140.5 1115.5,-937.67 ; 1737.5,-727.33 1737.5,-524 ; 2577.5,-727.33 2577.5,-524 ; 3844.5,-1134 3844.5,-524 ; 4733.5,-1134 6309,-1134 6309,-524 -292.5,-524 -292.5,-1134 2304.5,-1134 6309.5,-1134 6309.5,-524
  text "COMPONENTS MARKED 'DNP' SHOULD NOT BE POPULATED." at 6102,-318 h60
  text ".VariantName" at 5058,-434 h60
  text "ASSEMBLY VARIANT:" at 6097,-434 h60
  text ".VersionControl_RevNumber" at 1035.5,-656.17 h60
  text "SVN REV:" at 1541.5,-656.17 h60
  text ".PCB_Rev" at 2088,-656.17 h60
  text "REV:" at 2379.5,-656.17 h60
  text ".PRJ_Number" at 3224,-656.17 h60
  text "BOARD #:" at 3769.5,-656.17 h60
  text "PCB VIEWED FROM BOTTOM SIDE" at 6246,-656.17 h60
  text "IGNORE ->" at 2547.85,-858.49 h60
  text "TEXAS INSTRUMENTS" at 904.5,-1064.84 h60
  text ".Print_Time" at 2169,-1064.84 h60
  text ".Print_Date" at 2898,-1064.84 h60
  text "GENERATED    :" at 3767.5,-1064.84 h60
  text ".plot_File_Name" at 5440.5,-1064.84 h60
  text "PLOT NAME =" at 6246,-1064.84 h60
M9 Title Sheet:
  drawing of 57 lines, arcs and shapes, not listed
  text "1" at 739.84,8036.5 h70
  text "2" at 3235.5,8036.5 h70
  text "3" at 5724.84,8036.5 h70
  text "4" at 8231.51,8036.5 h70
  text "5" at 10730.5,8036.5 h70
  text "6" at 13235.5,8036.5 h70
  text "A" at -416.5,6893.5 h70
  text "A" at 14383.5,6893.5 h70
  text "B" at -416.5,4513.5 h70
  text "B" at 14383.5,4513.5 h70
  text "C" at -416.5,2138.5 h70
  text "C" at 14383.5,2138.5 h70
  text "PROJECT TITLE:" at 11343.5,277.5 h45
  text ".PRJ_Title" at 11393.5,144.17 h70
  text "DESIGNED FOR:" at 11343.5,-23.5 h45
  text ".PRJ_Customer" at 11393.5,-163.5 h70
  text "D" at -416.5,-231.5 h70
  text "D" at 14383.5,-231.5 h70
  text "FILE NAME:" at 11343.5,-323.5 h45
  text ".PCB_File_Name_No_Path" at 11393.5,-443.5 h70
  text "Texas Instruments (TI) and/or its licensors do not warrant the accuracy or completeness of this specification" at 6374,-605.34 h45
  text "ENGINEER:" at 11343.5,-613.5 h45
  text "LAYOUT BY:" at 12848.5,-613.5 h45
  text "or any information contained therein. TI and/or its licensors do not warrant that this design will meet" at 6329.01,-718 h45
  text ".PRJ_Engineer" at 11393.5,-768.49 h70
  text ".PCB_Layout" at 12899,-768.49 h70
  text "the specifications, will be suitable for your application or fit for any particular purpose, or will operate in" at 6329.01,-830.67 h45
  text ".Layer_Name" at 577,-858.49 h60
  text "ALTIUM DESIGNER VERSION:" at 12848.5,-923.5 h45
  text "an implementation. TI and/or its licensors do not warrant that the design is production worthy. You should" at 6329.01,-943.33 h45
  text "completely validate and test your design implementation to confirm the system functionality for your application." at 6374,-1056 h45
  text ".print_Scale" at 11393.5,-1056.83 h70
  text ".Application_BuildNumber" at 12899,-1056.83 h70
  text "1" at 739.84,-1263.5 h70
  text "2" at 3235.5,-1263.5 h70
  text "3" at 5724.84,-1263.5 h70
  text "4" at 8231.51,-1263.5 h70
  text "5" at 10730.5,-1263.5 h70
  text "6" at 13235.5,-1263.5 h70
M10 Fab Notes:
  drawing of 212 lines, arcs and shapes, not listed
  text "DESIGN INFORMATION" at 12381.02,6810 h60
  text "(REFER ALSO ARRAY/PANEL PROFILING INFORMATION)" at 12019.46,6648.29 h60
  text "BOARD SIZE" at 11333.46,6644 h60
  text "X" at 12301.46,6516.18 h60
  text "Number of Layers :" at 11736.46,6319 h60
  text "6" at 12831.27,6309 h60
  text "MIN. TRACK WIDTH:" at 11736.46,6180 h60
  text "8" at 12832.7,6180 h60
  text "MIL" at 12987.46,6180 h60
  text "MIN. CLEARANCE:" at 11736.46,6048 h60
  text "8" at 12832.7,6048 h60
  text "MIL" at 12987.46,6048 h60
  text "MIN. VIA PAD SIZE:" at 11736.46,5916 h60
  text "21" at 12802.71,5916 h60
  text "MIL" at 12987.46,5916 h60
  text "0.05mm (2MIL)" at 12431.46,5774.29 h60
  text "MINIMUM ANNULAR RING" at 11407.23,5770 h60
  text "EXTERNAL" at 13139.46,5770 h60
  text "PER" at 11607.23,5652 h60
  text "IPC-D-275 CLASS 2 LEVEL C" at 11827.23,5652 h60
  text "MIL, HOLES" at 13315.46,5539.71 h60
  text "+/-" at 12923,5539 h60
  text "+/-" at 13777,5539 h60
  text "REGISTRATION TOLERANCES:" at 11407.23,5534 h60
  text "METAL" at 12607,5534 h60
  text "5" at 13183.2,5534 h60
  text "3" at 14016.2,5534 h60
  text "MIL" at 14132.46,5534 h60
  text "MATERIAL:" at 11332.46,5324.54 h60
  text "FR-4 High Tg" at 12318.9,5184.21 h60
  text "FR-408" at 11753.46,5175.64 h60
  text "X" at 12165.46,5175.64 h60
  text "X" at 13054.46,5176 h60
  text "OTHER   ROGERS 4350" at 13241.46,5175.64 h60
  text "OTHER" at 13241.46,5175.64 h60
  text "62 MIL (1.6mm) +/-10%" at 12073.56,5012.92 h60
  text "THICKNESS:" at 11407.23,5008.64 h60
  text "X" at 11945.4,5008.64 h60
  text "OTHER" at 13358.46,5008.64 h60
  text "TOLERANCE:" at 11407.23,4850.64 h60
  text "X" at 12246.53,4850.64 h60
  text "ANSI IPC-6012 TYPE 3 CLASS 2" at 12433.48,4850.64 h60
  text "OTHER +/-" at 12433.46,4694.64 h60
  text "BOW & TWIST:" at 11407.23,4537.64 h60
  text "X" at 12246.53,4537.64 h60
  text "ANSI IPC-6012 TYPE 3 CLASS 2" at 12433.48,4537.64 h60
  text "OTHER +/-" at 12433.46,4379.13 h60
  text "COPPER THICKNESS (FINISHED):" at 11332.46,4243.64 h60
  text "1.4MIL (1oz)" at 12212.46,4090.92 h60
  text "2MIL (1.4oz)" at 12979.46,4090.92 h60
  text "2.8MIL (2oz)" at 13706.46,4090.92 h60
  text "OUTER:" at 11689.46,4086.64 h60
  text "X" at 12084,4086 h60
  text "1.4MIL (1oz)" at 12212.46,3933.92 h60
  text "2.8MIL (2oz)" at 12979.46,3933.92 h60
  text "N/A" at 13706,3934.29 h60
  text "INNER SIGNAL:" at 11400.38,3929.64 h60
  text "X" at 12085.42,3929.64 h60
  text "DRILLING:" at 11332.46,3790.64 h60
  text "REFERENCE:" at 11407.23,3673.64 h60
  text "X" at 12055.46,3673.64 h60
  text "AS SHOWN" at 12242.46,3673.64 h60
  text "X" at 12956.46,3673.64 h60
  text "NC_DRILL FILES" at 13093.46,3673.64 h60
  text "PTH MIN COPPER THICKNESS:" at 11407.23,3515.64 h60
  text "X" at 12757.46,3515.64 h60
  text "1MIL" at 12894.46,3515.64 h60
  text "OTHER" at 13391.46,3515.64 h60
  text "BOARD FINISH:" at 11332.46,3356.64 h60
  text "SILKSCREEN:" at 11487.68,3238.64 h60
  text "X" at 12436.46,3238.64 h60
  text "TOP" at 12562.46,3238.64 h60
  text "X" at 12946.46,3238.64 h60
  text "BOTTOM" at 13073.46,3238.64 h60
  text "SILKSCREEN COLOR:" at 11487.68,3071.64 h60
  text "X" at 12435.42,3071.64 h60
  text "WHITE" at 12562.46,3071.64 h60
  text "OTHER" at 13073.46,3071.64 h60
  text "SOLDER RESIST COLOR:" at 11487.68,2901.64 h60
  text "X" at 12055.42,2742.44 h60
  text "GREEN" at 12182.46,2742.44 h60
  text "BLUE" at 12773.46,2742.44 h60
  text "OTHER" at 13311.46,2742.44 h60
  text "IMMERSION GOLD (ENIG)" at 12393.46,2553.92 h60
  text "ENEPIG" at 13731,2550.64 h60
  text "SURFACE FINISH:" at 11332.46,2549.64 h60
  text "X" at 12206.51,2549.64 h60
  text "IMM. TIN/SILVER OR EQUIV" at 11662,2392.64 h60
  text "OTHER" at 13093.46,2392.64 h60
  text "ARRAY/PANEL:" at 11332.46,2213.64 h60
  text "X" at 12206.46,2213.64 h60
  text "CUT AND TRIM PER MECH LAYER 1" at 12393.46,2209.35 h60
  text "N.C. ROUTE" at 12393.46,2057.64 h60
  text "V. SCORE" at 13259.46,2057.64 h60
  text "CERTIFICATION:" at 11332.46,1920.64 h60
  text "MATERIALS AND WORKMANSHIP FOR ALL PCBS" at 12057.46,1920.64 h60
  text "TO MEET OR EXCEED THE REQUIREMENTS OF:" at 12057.46,1822.64 h60
  text "X" at 11683.96,1686.13 h60
  text "ANSI IPC-A-600F CLASS ->" at 11822.96,1686.13 h60
  text "X" at 13462.02,1686.13 h60
  text "2" at 13580.96,1686.14 h60
  text "1" at 13265.96,1684.64 h60
  text "3" at 13934.96,1684.64 h60
  text "X" at 11686.02,1526.64 h60
  text "UL 94V-0" at 11822.96,1526.64 h60
  text "X" at 12498.02,1526.64 h60
  text "RoHS" at 12634.96,1526.64 h60
  text "OTHER" at 13279.36,1526.64 h60
  text "PER ORDER" at 13676.42,1526.64 h60
  text "Single ended tracks 50 ohms Top Layer equal 35mils width." at 2594,1500 h100
  text "ADDITIONAL REQUIREMENTS:" at 11332.46,1385.64 h60
  text "MICROSECTION:" at 11407.23,1270.64 h60
  text "YES" at 12312.96,1270.64 h60
  text "REQUIRED" at 13174.46,1114.49 h60
  text "BARE BOARD ELEC. TEST:" at 11407.23,1111.64 h60
  text "NONE" at 12712.96,1111.64 h60
  text "X" at 13047.46,1111.64 h60
  text "PER ORDER" at 13766.46,1111.64 h60
  text "MANUFACTURER'S UL:" at 11407.23,954.64 h60
  text "RAIL" at 12572.96,950.35 h60
  text "METAL" at 13064.77,950.35 h60
  text "X" at 13440,950 h60
  text "SILK" at 13576.46,950.35 h60
  text ".Layer_Name" at 577,-858.49 h60
M11 Gerber Information:
  lines w10: -292,-930.17 6308,-930.17 ; -292,-726.83 6310,-726.83 ; -292,-523.5 -292,-1133.5 3713,-1133.5 6310,-1133.5 6310,-523.5 -291.5,-523.5 -291.5,-1133.5 1284,-1133.5 ; 2173,-1133.5 2173,-523.5 ; 3440,-726.83 3440,-523.5 ; 4280,-726.83 4280,-523.5 ; 4902,-1140 4902,-937.17
  text "ALL ARTWORK VIEWED FROM TOP SIDE" at -228.5,-655.67 h60
  text "BOARD #:" at 2248,-655.67 h60
  text ".PRJ_Number" at 2793.5,-655.67 h60
  text "REV:" at 3638,-655.67 h60
  text ".PCB_Rev" at 3929.5,-655.67 h60
  text "SVN REV:" at 4476,-655.67 h60
  text ".VersionControl_RevNumber" at 4982,-655.67 h60
  text "LAYER NAME =" at -228.5,-858.49 h60
  text "PLOT NAME =" at -228.5,-1064.34 h60
  text ".plot_File_Name" at 577,-1064.34 h60
  text "GENERATED    :" at 2250,-1064.34 h60
  text ".Print_Date" at 3119.5,-1064.34 h60
  text ".Print_Time" at 3848.5,-1064.34 h60
  text "TEXAS INSTRUMENTS" at 5113,-1064.34 h60
M12 Stackup:
  lines w5: 11362,7748.1 14230,7748.1 ; 11362,7843.3 14230,7843.3 ; 11302,6967 ccw(c11333,6967) 11333,6936 14259,6936 ccw(c14259,6967) 14290,6967 14290,7917 ccw(c14259,7917) 14259,7948 11333,7948 ccw(c11333,7917) 11302,7917 11302,6967
  text "Layer Stack Up Detail for: CASCADED_LMH5401_EVM-A.PcbDoc" at 11362,7866.15 h40
  text "Layer" at 11362,7807.8 h22
  text "Gerber" at 11973.83,7807.8 h22
  text "Copper" at 12285.82,7807.8 h22
  text "Dielectric" at 12633.74,7807.8 h22
  text "Dielectric" at 12997.05,7807.8 h22
  text "Dielectric" at 13453.93,7807.8 h22
  text "Dielectric" at 13817.24,7807.8 h22
  text "Name" at 11362,7763.8 h22
  text "Document" at 11973.83,7763.8 h22
  text "Thickness" at 12285.82,7763.8 h22
  text "Height" at 12633.74,7763.8 h22
  text "Material" at 12997.05,7763.8 h22
  text "Constant" at 13453.93,7763.8 h22
  text "Type" at 13817.24,7763.8 h22
  text "Top Solder Mask" at 11362,7701.33 h31
  text "(.GTS)" at 11973.83,7701.33 h31
  text "0.4mil" at 12633.74,7701.33 h31
  text "Solder Resist" at 12997.05,7701.33 h31
  text "3.50" at 13453.93,7701.33 h31
  text "Top Layer L1" at 11362,7612.77 h31
  text "(.GTL)" at 11973.83,7612.77 h31
  text "1.4mil" at 12285.82,7612.77 h31
  text "10mil" at 12633.74,7568.5 h31
  text "Rogers RO4350" at 12997.05,7568.5 h31
  text "3.66" at 13453.93,7568.5 h31
  text "Core" at 13817.24,7568.5 h31
  text "Layer 2 GND L2" at 11362,7524.23 h31
  text "(.GP1)" at 11973.83,7524.23 h31
  text "1.4mil" at 12285.82,7524.23 h31
  text "10mil" at 12633.74,7479.95 h31
  text "FR406" at 12997.05,7479.95 h31
  text "4.80" at 13453.93,7479.95 h31
  text "PrePreg" at 13817.24,7479.95 h31
  text "Layer 3 V+ L3" at 11362,7435.67 h31
  text "(.GP2)" at 11973.83,7435.67 h31
  text "1.4mil" at 12285.82,7435.67 h31
  text "12mil" at 12633.74,7391.4 h31
  text "FR406" at 12997.05,7391.4 h31
  text "4.80" at 13453.93,7391.4 h31
  text "Core" at 13817.24,7391.4 h31
  text "Layer 4 V- L4" at 11362,7347.12 h31
  text "(.GP3)" at 11973.83,7347.12 h31
  text "1.4mil" at 12285.82,7347.12 h31
  text "10mil" at 12633.74,7302.85 h31
  text "FR406" at 12997.05,7302.85 h31
  text "4.80" at 13453.93,7302.85 h31
  text "PrePreg" at 13817.24,7302.85 h31
  text "Layer 5 GND L5" at 11362,7258.58 h31
  text "(.GP4)" at 11973.83,7258.58 h31
  text "1.4mil" at 12285.82,7258.58 h31
  text "10mil" at 12633.74,7214.3 h31
  text "FR406" at 12997.05,7214.3 h31
  text "4.80" at 13453.93,7214.3 h31
  text "Core" at 13817.24,7214.3 h31
  text "Bottom Layer L6" at 11362,7170.02 h31
  text "(.GBL)" at 11973.83,7170.02 h31
  text "1.4mil" at 12285.82,7170.02 h31
  text "Bottom Solder Mask" at 11362,7081.48 h31
  text "(.GBS)" at 11973.83,7081.48 h31
  text "0.4mil" at 12633.74,7081.48 h31
  text "Solder Resist" at 12997.05,7081.48 h31
  text "3.50" at 13453.93,7081.48 h31
  text ".Layer_Name" at 577,-858.49 h60
M13 Component Bodies Top:
  text ".Layer_Name" at 577,-858.49 h60
M14 Component Bodies Bottom:
  text ".Layer_Name" at 577,-858.49 h60
M15 Courtyards Top:
  text ".Layer_Name" at 577,-858.49 h60
M16 Courtyards Bottom:
  text ".Layer_Name" at 577,-858.49 h60
Drill Drawing:
  text ".legend" at 5122.5,725.5 h60
  text "Drill Table" at 5147.5,540.5 h60
  text ".Layer_Name" at 577,-858.49 h60

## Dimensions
0,0 to 1606,0 on M2 Board Dimensions
0,0 to 0,1500 on M2 Board Dimensions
